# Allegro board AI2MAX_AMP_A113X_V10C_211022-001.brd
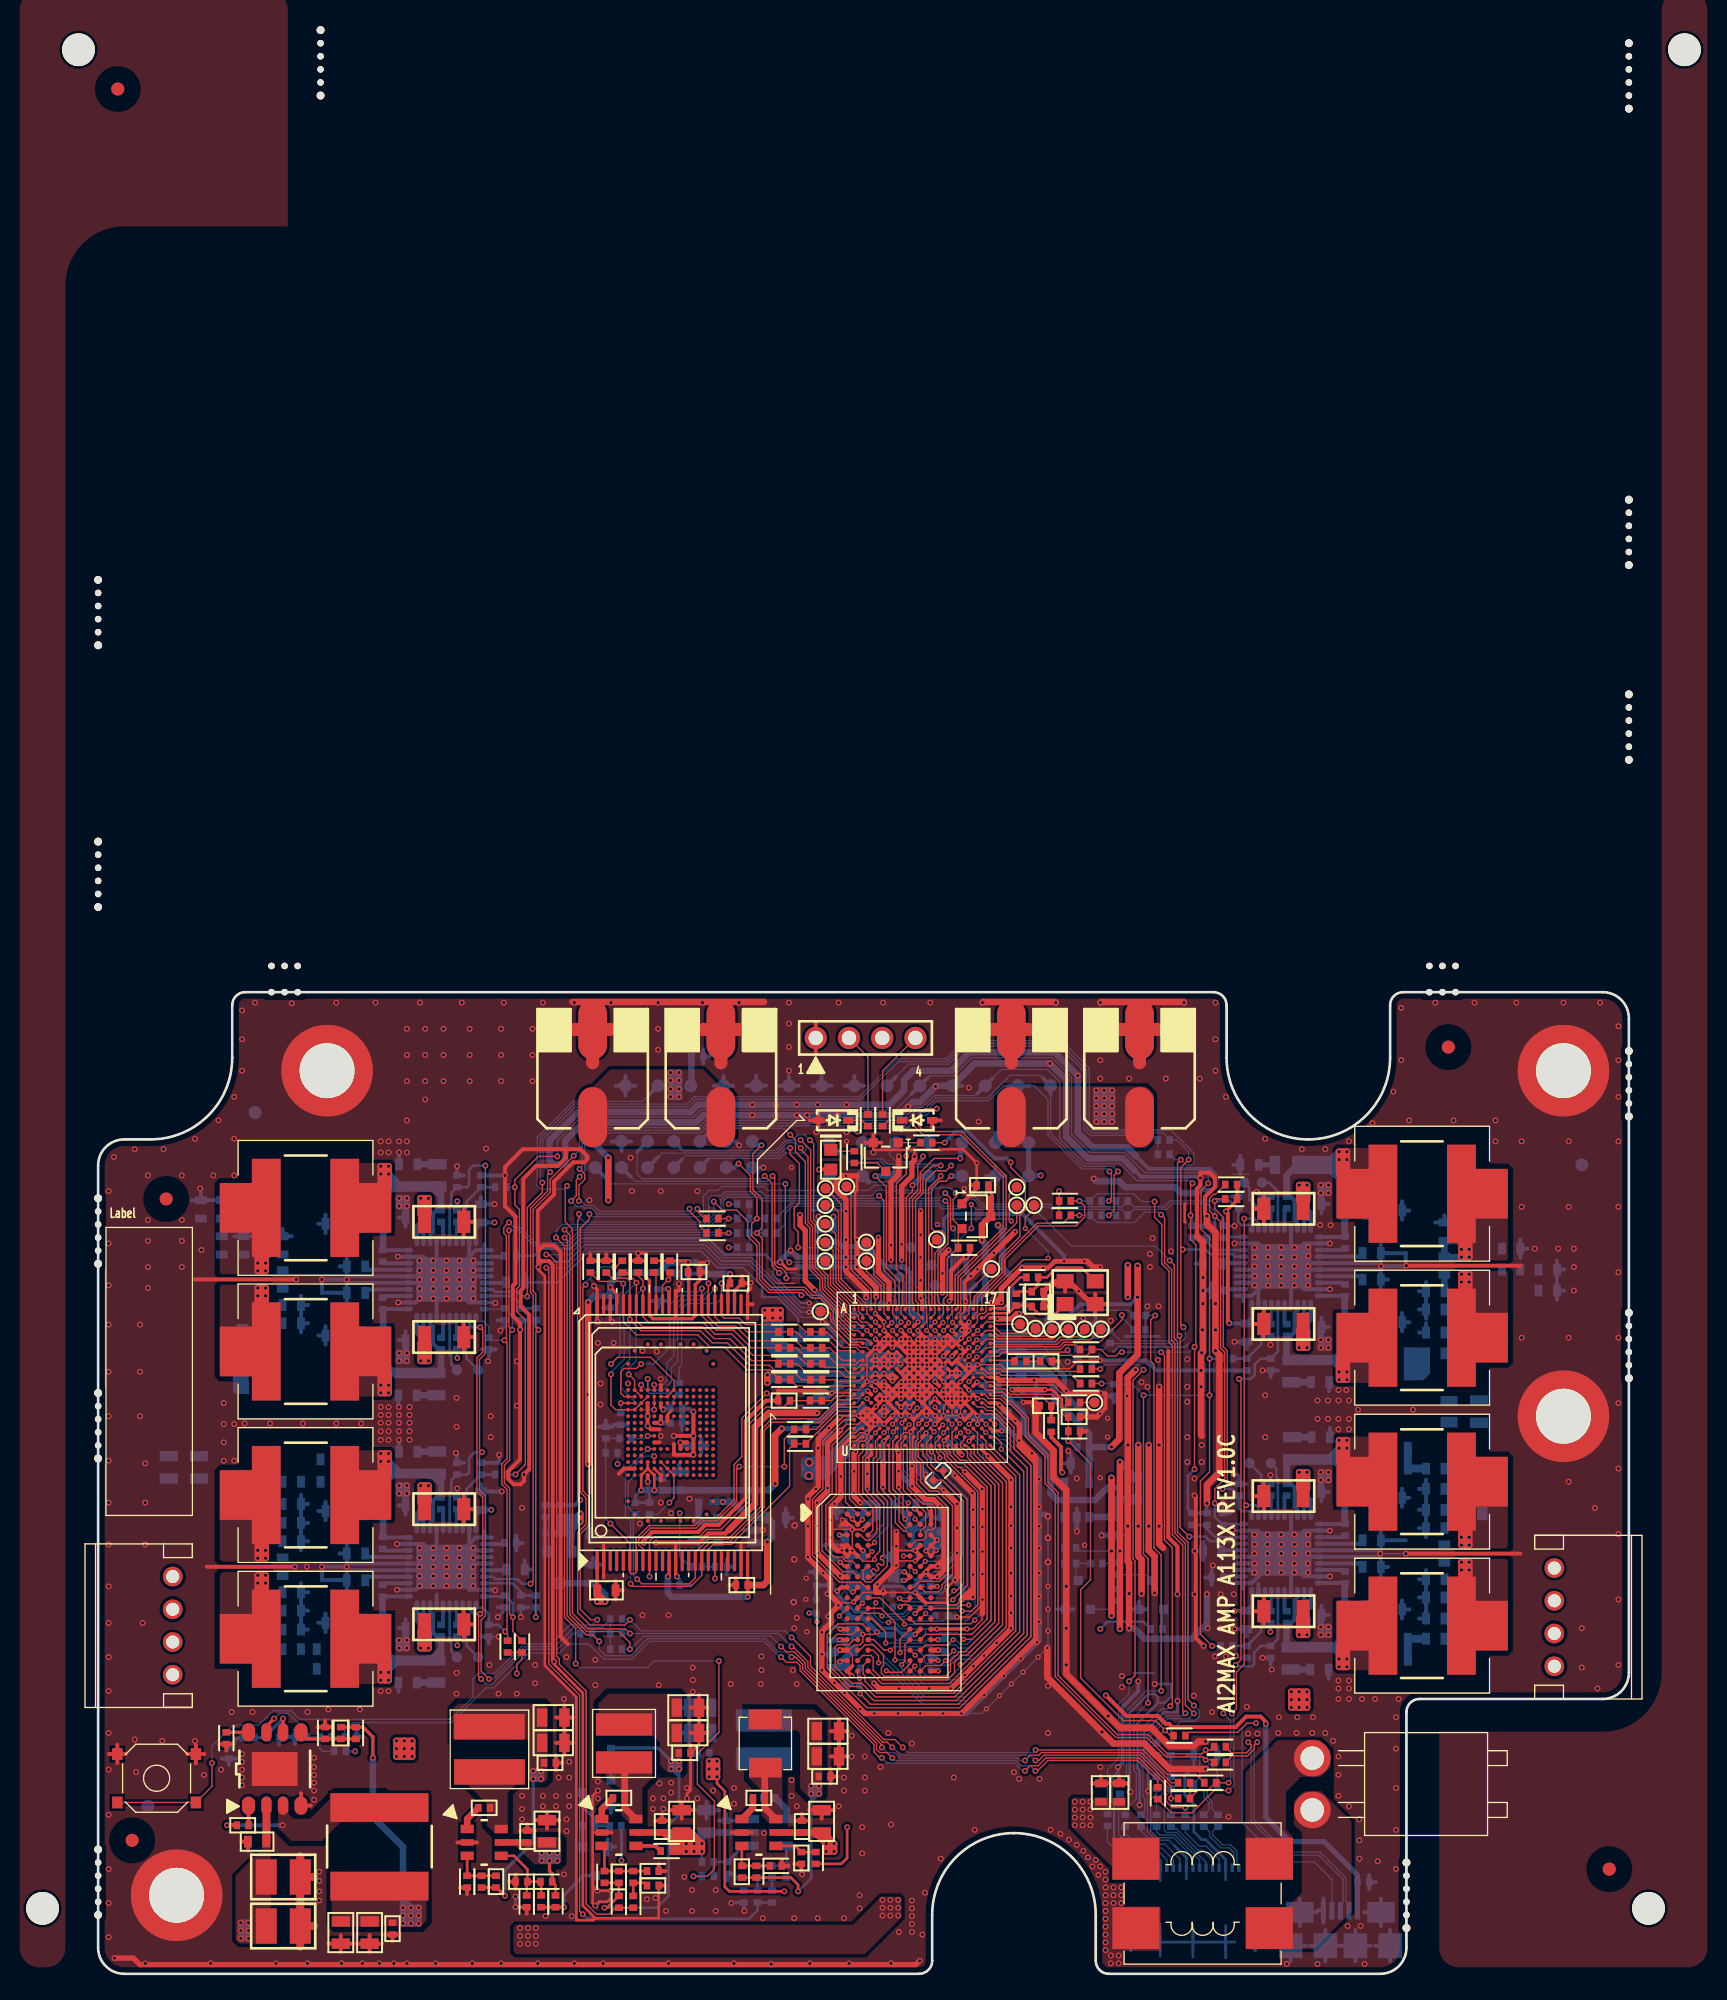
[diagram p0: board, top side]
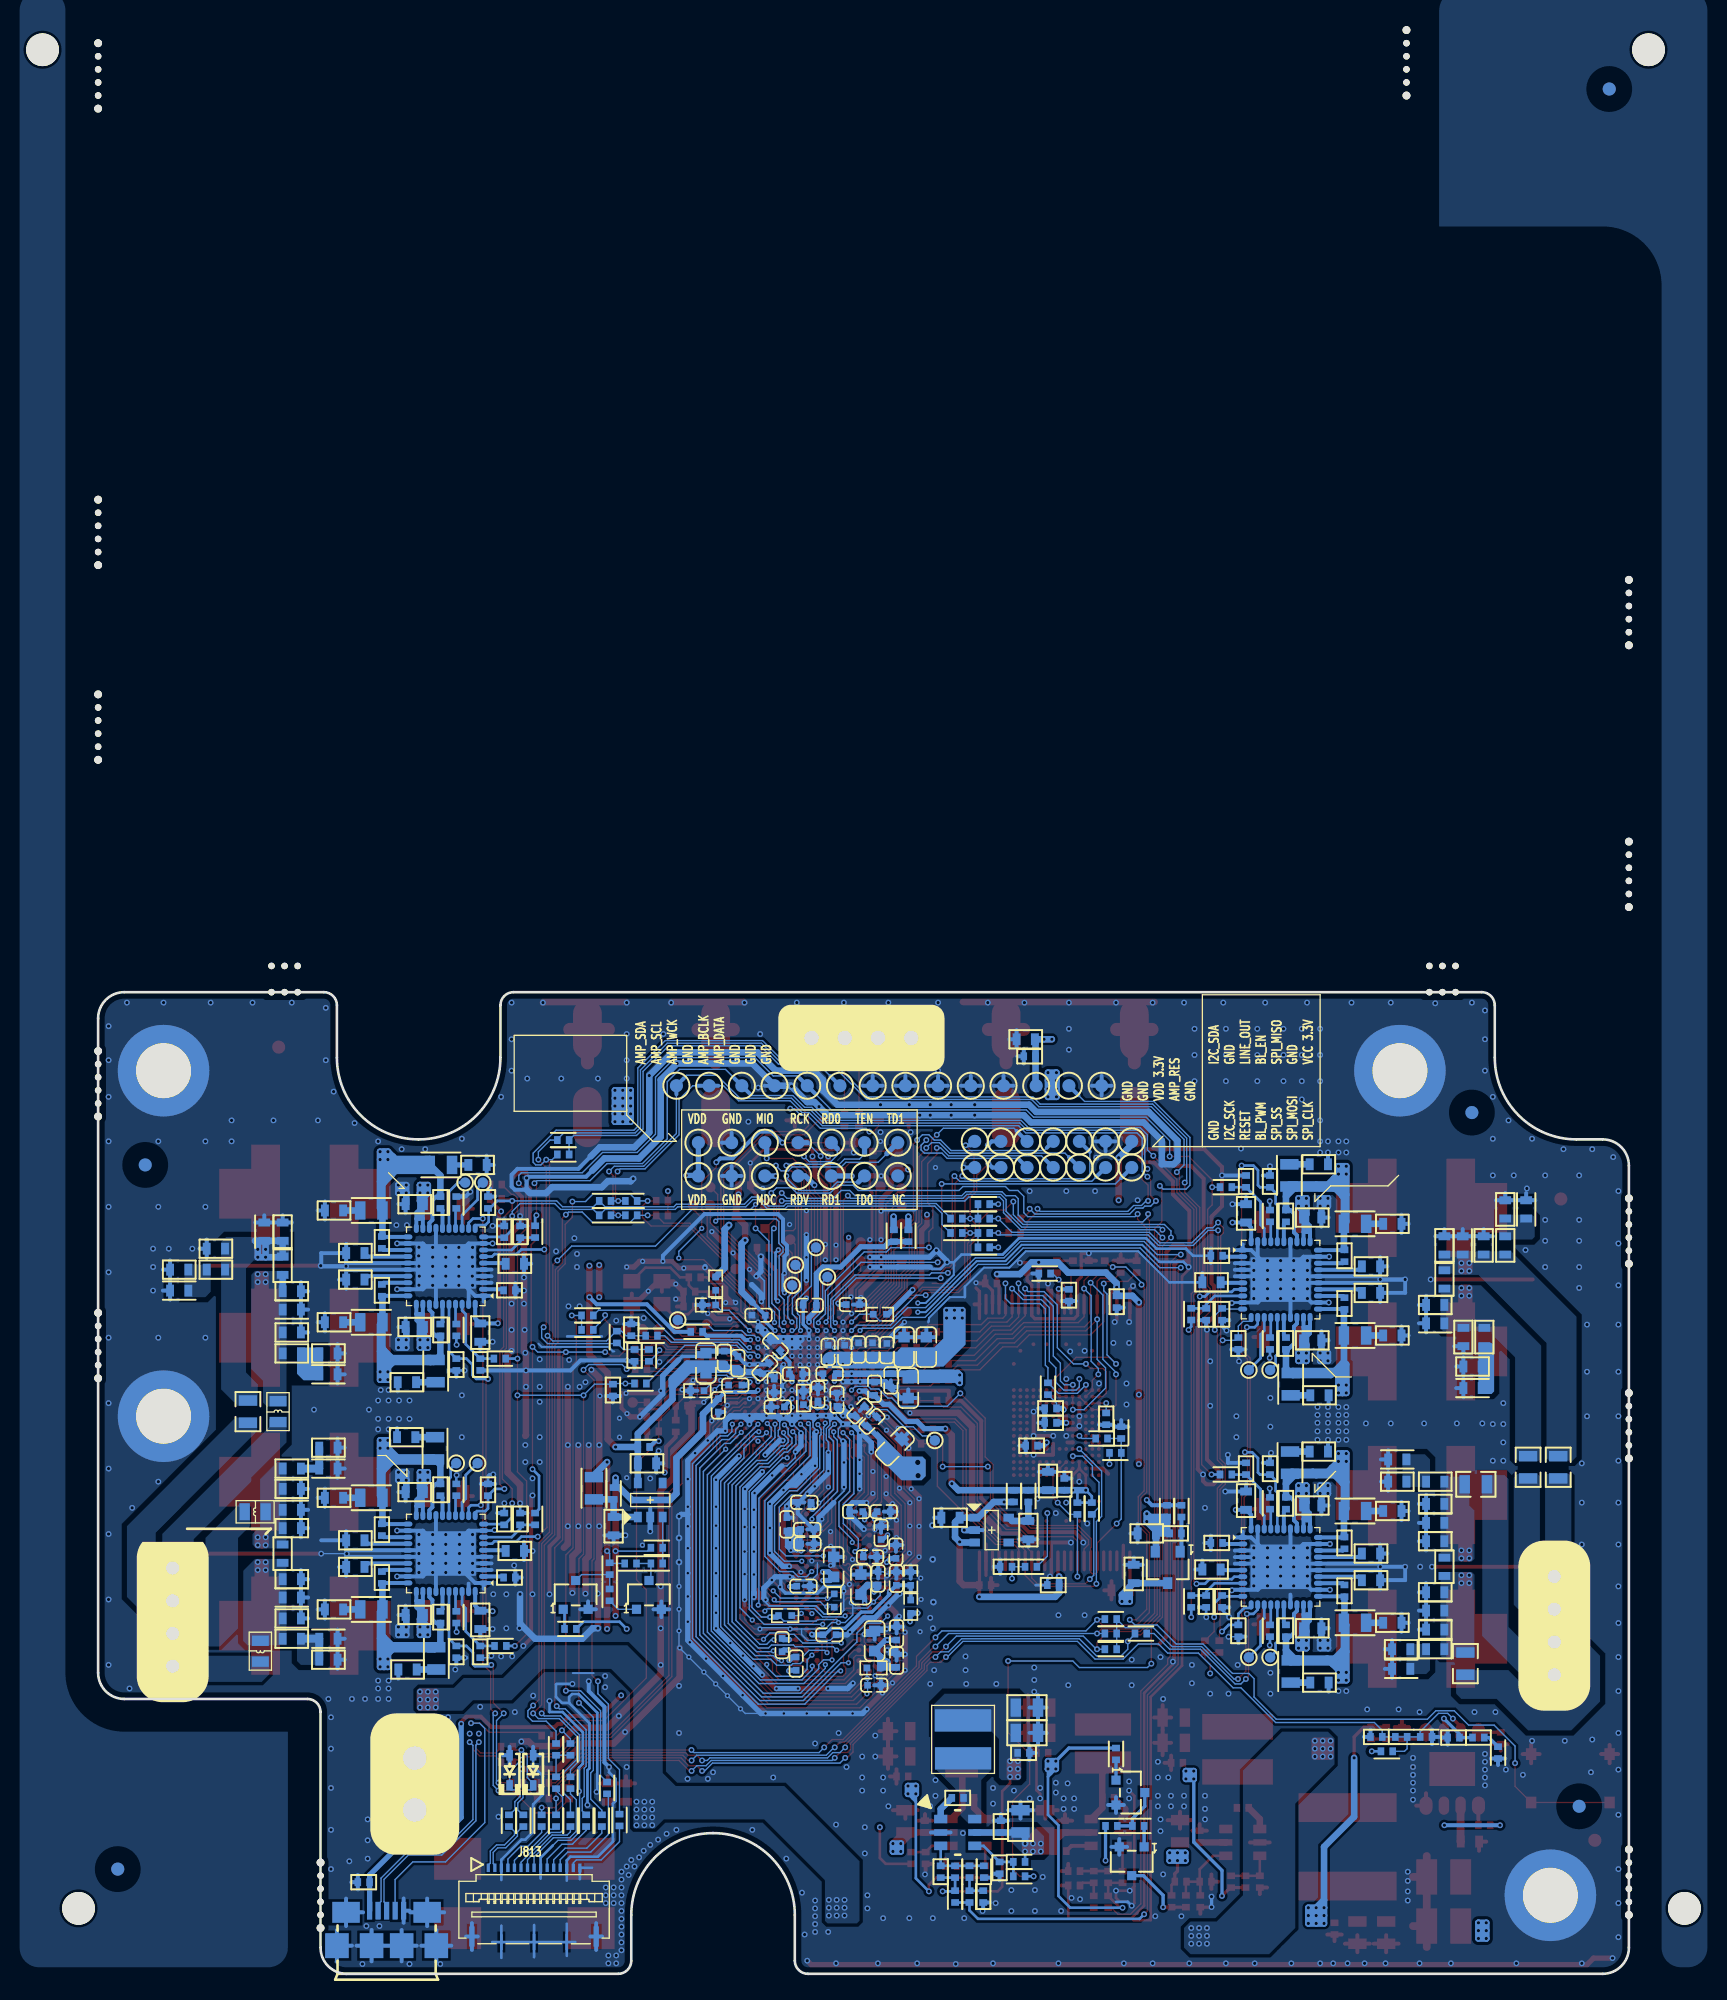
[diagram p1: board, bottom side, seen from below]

Outline 117 x 75 mm; copper layers: TOP, MID1(L2), MID2(L3), BOTTOM. Coordinates in mm from the lower left corner of the outline.
Outline path: 0,61.75 arc(0.59,63.16) 2,63.75 4,63.75 arc(8.42,65.58) 10.25,70 10.25,74 arc(10.54,74.71) 11.25,75 85.25,75 arc(85.96,74.71) 86.25,74 86.25,70 arc(88.08,65.58) 92.5,63.75 arc(96.92,65.58) 98.75,70 98.75,74 arc(99.04,74.71) 99.75,75 115,75 arc(116.41,74.41) 117,73 117,23 arc(116.41,21.59) 115,21 101,21 arc(100.29,20.71) 100,20 100,2 arc(99.41,0.59) 98,0 77.25,0 arc(76.54,0.29) 76.25,1 76.25,4.5 arc(74.42,8.92) 70,10.75 arc(65.58,8.92) 63.75,4.5 63.75,1 arc(63.46,0.29) 62.75,0 2,0 arc(0.59,0.59) 0,2 0,61.75

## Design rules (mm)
net group I2S1: nets BCLK DATA LRCK
net group POWER: nets N21714583 N21714673 N21714779 N21715058 N21715192 N21715315 N21715441 N21715523 N21715623 N21715900 N21716032 N21716155 N21722582 N21722669 N21722769 N21723040 N21723161 N21723285 N21723494 N21723601 N21723713 N21724007 N21727322 N21727332
net group USBOTG_A_DM: nets N21775203 N22017810 USBOTG_A_DM
net group USBOTG_A_DP: nets N21775223 N22060831 USBOTG_A_DP

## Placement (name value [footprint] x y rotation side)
C1  105P/50V/1608  [C1608]  78.05 13.85 90 top
C2  104P/50V/1608  [C1608]  76.65 13.85 90 top
C3  106P/50V/3225  [C3225]  14.15 7.4 0 top
C4  104P/50V/1608  [C1608]  12.15 10.1 180 top
C5  104P/16V/1005  [C1005]  11.05 11.35 180 top
C6  226P/10V/2012  [C2012]  18.55 3.15 270 top
C7  226P/10V/2012  [C2012]  20.75 3.15 270 top
C9  104P/16V/1005  [C1005]  22.5 3.45 90 top
C10  100P/50V/1005  [C1005]  18.55 18.4 90 top
C12  OPEN-104P/16V/1005  [C1005]  19.3 18.1 180 bottom
C13  226P/10V/2012  [C2012]  34.31 10.89 90 top
C14  104P/16V/1005  [C1005]  32.81 10.49 270 top
C15  104P/16V/1005  [C1005]  29.51 12.68 0 top
C16  226P/6.3V/2012  [C2012]  34.79 19.58 0 top
C17  104P/16V/1005  [C1005]  34.54 16.12 180 top
C18  226P/6.3V/2012  [C2012]  34.79 17.65 0 top
C19  330P/50V/1005  [C1005]  30.41 7.04 270 top
C20  104P/16V/1005  [C1005]  32.36 7.04 0 top
C21  106P/6.3V/1608  [C1608]  36.85 33.65 0 bottom
C22  106P/6.3V/1608  [C1608]  37.85 30.55 90 bottom
C23  104P/16V/1005  [C1005]  34.65 33.65 0 bottom
C24  682P/50V/1005  [C1005]  11.5 18.05 0 bottom
C25  100P/50V/1005  [C1005]  13.4 18.05 180 bottom
C30  106P/50V/3225  [C3225]  14.15 3.65 0 top
C51  226P/10V/2012  [C2012]  46.5 11.65 90 bottom
C52  104P/16V/1005  [C1005]  48 11.25 270 bottom
C53  104P/16V/1005  [C1005]  51.3 13.44 180 bottom
C54  226P/6.3V/2012  [C2012]  46.01 20.34 180 bottom
C55  104P/16V/1005  [C1005]  46.27 16.88 0 bottom
C56  226P/6.3V/2012  [C2012]  46.01 18.41 180 bottom
C57  226P/10V/2012  [C2012]  44.6 11.65 90 top
C58  104P/16V/1005  [C1005]  43.1 11.25 270 top
C59  104P/16V/1005  [C1005]  39.8 13.44 0 top
C60  226P/6.3V/2012  [C2012]  45.08 20.34 0 top
C61  104P/16V/1005  [C1005]  44.83 16.88 180 top
C62  226P/6.3V/2012  [C2012]  45.08 18.41 0 top
C63  270P/50V/1005  [C1005]  52.6 7.8 270 bottom
C64  270P/50V/1005  [C1005]  39.8 7.4 270 top
C65  104P/16V/1005  [C1005]  48.1 8.1 90 bottom
C66  102P/16V/1005  [C1005]  49.35 5.9 90 bottom
C67  102P/16V/1005  [C1005]  42.4 6.75 180 top
C68  226P/10V/2012  [C2012]  55.3 11.65 90 top
C69  104P/16V/1005  [C1005]  53.8 11.25 270 top
C70  104P/16V/1005  [C1005]  50.5 13.44 0 top
C71  226P/6.3V/2012  [C2012]  55.78 18.54 0 top
C72  104P/16V/1005  [C1005]  55.53 15.08 180 top
C73  226P/6.3V/2012  [C2012]  55.78 16.61 0 top
C74  330P/50V/1005  [C1005]  49.2 7.8 270 top
C75  OPEN-104P/16V/1005  [C1005]  53.75 8.85 90 top
C76  106P/6.3V/1608  [C1608]  75.05 39 180 bottom
C77  OPEN-106P/6.3V/1608  [C1608]  45.9 33.9 270 bottom
C78  472P/50V/1608  [C1608]  77.6 34.2 270 bottom
C79  OPEN-472P/50V/1608  [C1608]  51.85 34.85 0 bottom
C101  104P/16V/1005  [C0402]  69.6 43.43 90 bottom
C102  105P/6.3V/1005  [C0402]  62.61 51.08 180 bottom
C103  OPEN-150P/50V/1005  [C1005]  77.65 44.6 90 bottom
C104  OPEN-150P/50V/1005  [C1005]  72.45 46.8 180 top
C105  270P/50V/1005  [C1005]  76 47.25 90 bottom
C106  270P/50V/1005  [C1005]  76.25 49.2 270 bottom
C201  105P/6.3V/1608  [C1608]  87.79 48.99 270 bottom
C202  223P/16V/1005  [C1005]  90.84 49.19 270 bottom
C203  271P/50V/1608  [C1608]  93.4 45.2 180 bottom
C204  104P/16V/1005  [C1005]  89.62 46.55 90 bottom
C205  100uF/35V/CLZ  [ECAP_8PI_H10]  47.6 68.8 270 top
C206  104P/50V/1608  [C1608]  92.8 49.42 0 bottom
C207  271P/50V/1608  [C1608]  98.97 49.78 180 bottom
C208  OPEN-104P/16V/1005  [C1005]  85.56 52.22 0 bottom
C209  105P/50V/1608  [C1608]  102.2 52.15 180 bottom
C210  223P/16V/1005  [C1005]  95.31 52.22 90 bottom
C211  105P/16V/1608  [C1608]  97.34 53.04 0 bottom
C213  471P/50V/1608  [C1608]  102.9 54.1 90 bottom
C214  105P/16V/1608  [C1608]  97.34 55.07 0 bottom
C215  223P/16V/1005  [C1005]  95.31 55.88 270 bottom
C216  105P/50V/1608  [C1608]  102.9 56.7 270 bottom
C217  330P/50V/1005  [C1005]  85.96 56.69 270 bottom
C218  105P/6.3V/1608  [C1608]  85.15 54.25 180 bottom
C219  271P/50V/1608  [C1608]  98.97 58.32 180 bottom
C220  223P/16V/1005  [C1005]  90.84 58.93 270 bottom
C221  271P/50V/1608  [C1608]  88 61.8 0 bottom
C222  330P/50V/1005  [C1005]  87.2 58.93 270 bottom
C223  100uF/35V/CLZ  [ECAP_8PI_H10]  37.8 68.8 270 top
C224  104P/50V/1608  [C1608]  92.8 58.8 0 bottom
C225  223P/16V/1005  [C1005]  90.84 27.25 270 bottom
C226  104P/16V/1005  [C1005]  89.62 24.6 90 bottom
C228  271P/50V/1608  [C1608]  93.35 23.25 180 bottom
C229  271P/50V/1608  [C1608]  98.97 27.84 180 bottom
C230  105P/6.3V/1608  [C1608]  87.79 27.04 270 bottom
C231  104P/50V/1608  [C1608]  92.8 27.42 0 bottom
C232  OPEN-104P/16V/1005  [C1005]  85.56 30.28 0 bottom
C233  105P/50V/1608  [C1608]  102.2 30.15 180 bottom
C234  223P/16V/1005  [C1005]  95.31 30.28 90 bottom
C235  105P/16V/1608  [C1608]  97.34 31.09 0 bottom
C237  471P/50V/1608  [C1608]  102.9 32.1 90 bottom
C238  105P/16V/1608  [C1608]  97.34 33.12 0 bottom
C239  223P/16V/1005  [C1005]  95.31 33.93 270 bottom
C240  105P/50V/1608  [C1608]  102.2 34.05 0 bottom
C241  330P/50V/1005  [C1005]  85.96 34.75 270 bottom
C242  105P/6.3V/1608  [C1608]  85.15 32.31 180 bottom
C243  271P/50V/1608  [C1608]  98.97 36.37 180 bottom
C244  223P/16V/1005  [C1005]  90.84 36.98 270 bottom
C245  271P/50V/1608  [C1608]  93.45 41 180 bottom
C246  330P/50V/1005  [C1005]  87.2 36.98 270 bottom
C248  104P/50V/1608  [C1608]  92.8 36.8 0 bottom
C249  OPEN-105P/6.3V/1608  [C1608]  46.1 71.4 0 bottom
C250  OPEN-104P/16V/1005  [C1005]  45.8 70.1 180 bottom
C251  OPEN-330P/50V/1005  [C1005]  87.79 46.55 90 bottom
C252  OPEN-330P/50V/1005  [C1005]  84.74 56.69 270 bottom
C253  OPEN-330P/50V/1005  [C1005]  87.79 24.6 90 bottom
C254  OPEN-330P/50V/1005  [C1005]  84.74 34.75 270 bottom
C255  106P/35V/3216  [C3216]  90.6 49.65 180 top
C256  106P/35V/3216  [C3216]  90.6 58.45 180 top
C257  106P/35V/3216  [C3216]  90.6 27.7 180 top
C258  106P/35V/3216  [C3216]  90.6 36.5 180 top
C259  121P/50V/1608  [C1608]  102.2 49 0 bottom
C260  121P/50V/1608  [C1608]  108 55.4 0 bottom
C261  121P/50V/1608  [C1608]  102.2 27.15 0 bottom
C262  121P/50V/1608  [C1608]  102.2 37.05 180 bottom
C263  OPEN-224P/50V/1608  [C1608]  102.2 47.4 180 bottom
C264  OPEN-224P/50V/1608  [C1608]  99.4 47.4 180 bottom
C265  OPEN-224P/50V/1608  [C1608]  110.8 53.8 180 bottom
C266  OPEN-224P/50V/1608  [C1608]  108 53.8 180 bottom
C267  OPEN-224P/50V/1608  [C1608]  102.2 25.6 180 bottom
C268  OPEN-224P/50V/1608  [C1608]  99.4 24 180 bottom
C269  OPEN-224P/50V/1608  [C1608]  99.4 40.2 0 bottom
C270  OPEN-224P/50V/1608  [C1608]  102.2 38.6 0 bottom
C301  105P/6.3V/1608  [C1608]  29.26 36.15 90 bottom
C302  223P/16V/1005  [C1005]  26.21 35.95 90 bottom
C303  271P/50V/1608  [C1608]  23.7 39.9 0 bottom
C304  104P/16V/1005  [C1005]  27.43 38.59 270 bottom
C305  100uF/35V/CLZ  [ECAP_8PI_H10]  69.8 68.8 270 top
C306  104P/50V/1608  [C1608]  24.2 35.78 180 bottom
C307  271P/50V/1608  [C1608]  18.08 35.36 0 bottom
C308  OPEN-104P/16V/1005  [C1005]  31.5 32.92 180 bottom
C309  105P/50V/1608  [C1608]  14.8 33.05 0 bottom
C310  223P/16V/1005  [C1005]  21.74 32.92 270 bottom
C311  105P/16V/1608  [C1608]  19.71 32.11 180 bottom
C313  471P/50V/1608  [C1608]  14.1 31.1 270 bottom
C314  105P/16V/1608  [C1608]  19.71 30.07 180 bottom
C315  223P/16V/1005  [C1005]  21.74 29.26 90 bottom
C316  105P/50V/1608  [C1608]  14.8 29.15 180 bottom
C317  330P/50V/1005  [C1005]  31.09 28.45 90 bottom
C318  105P/6.3V/1608  [C1608]  31.9 30.89 0 bottom
C319  271P/50V/1608  [C1608]  18.08 26.82 0 bottom
C320  223P/16V/1005  [C1005]  26.21 26.21 90 bottom
C321  271P/50V/1608  [C1608]  23.65 22.25 0 bottom
C322  330P/50V/1005  [C1005]  29.85 26.21 90 bottom
C323  100uF/35V/CLZ  [ECAP_8PI_H10]  79.6 68.8 270 top
C324  104P/50V/1608  [C1608]  24.2 26.4 180 bottom
C325  223P/16V/1005  [C1005]  26.21 57.9 90 bottom
C326  104P/16V/1005  [C1005]  27.43 60.54 270 bottom
C328  271P/50V/1608  [C1608]  23.7 61.85 0 bottom
C329  271P/50V/1608  [C1608]  18.08 57.3 0 bottom
C330  105P/6.3V/1608  [C1608]  29.26 58.1 90 bottom
C331  104P/50V/1608  [C1608]  24.2 57.78 180 bottom
C332  OPEN-104P/16V/1005  [C1005]  31.5 54.86 180 bottom
C333  105P/50V/1608  [C1608]  14.1 55.65 90 bottom
C334  223P/16V/1005  [C1005]  21.74 54.86 270 bottom
C335  105P/16V/1608  [C1608]  19.71 54.05 180 bottom
C337  471P/50V/1608  [C1608]  14.1 53.05 270 bottom
C338  105P/16V/1608  [C1608]  19.71 52.02 180 bottom
C339  223P/16V/1005  [C1005]  21.74 51.21 90 bottom
C340  105P/50V/1608  [C1608]  14.8 51.1 180 bottom
C341  330P/50V/1005  [C1005]  31.09 50.39 90 bottom
C342  105P/6.3V/1608  [C1608]  31.9 52.83 0 bottom
C343  271P/50V/1608  [C1608]  18.08 48.77 0 bottom
C344  223P/16V/1005  [C1005]  26.21 48.16 90 bottom
C345  271P/50V/1608  [C1608]  23.65 44.2 0 bottom
C346  330P/50V/1005  [C1005]  29.85 48.16 90 bottom
C348  104P/50V/1608  [C1608]  24.2 48.4 180 bottom
C349  OPEN-330P/50V/1005  [C1005]  29.26 38.59 270 bottom
C350  OPEN-330P/50V/1005  [C1005]  32.31 28.45 90 bottom
C351  OPEN-330P/50V/1005  [C1005]  29.26 60.54 270 bottom
C352  OPEN-330P/50V/1005  [C1005]  32.31 50.39 90 bottom
C353  106P/35V/3216  [C3216]  26.45 35.5 0 top
C354  106P/35V/3216  [C3216]  26.45 26.7 0 top
C355  106P/35V/3216  [C3216]  26.45 57.45 0 top
C356  106P/35V/3216  [C3216]  26.45 48.65 0 top
C357  121P/50V/1608  [C1608]  14.8 35.9 180 bottom
C358  121P/50V/1608  [C1608]  14.8 26.3 0 bottom
C359  121P/50V/1608  [C1608]  11.1 55.65 270 bottom
C360  121P/50V/1608  [C1608]  12.65 48.65 270 bottom
C361  OPEN-224P/50V/1608  [C1608]  14.8 37.6 0 bottom
C362  OPEN-224P/50V/1608  [C1608]  17.7 37.6 0 bottom
C363  OPEN-224P/50V/1608  [C1608]  17.4 24.8 180 bottom
C364  OPEN-224P/50V/1608  [C1608]  14.8 24.8 180 bottom
C365  OPEN-224P/50V/1608  [C1608]  9.45 55.65 90 bottom
C366  OPEN-224P/50V/1608  [C1608]  9.45 58.4 90 bottom
C367  OPEN-224P/50V/1608  [C1608]  11.95 46.4 180 bottom
C368  OPEN-224P/50V/1608  [C1608]  11.05 48.65 90 bottom
FB201  CIS21J121NE  [CIS2012]  105.55 42.95 90 bottom
FB202  120ohm/5A/2012  [BLM21]  103.25 42.95 90 bottom
FB203  120ohm/5A/2012  [BLM21]  104.6 24.65 270 bottom
FB204  120ohm/5A/2012  [BLM21]  105 35.3 0 bottom
FB301  CIS21J121NE  [CIS2012]  12.5 23.7 90 bottom
FB302  CIS21J121NE  [CIS2012]  11.7 37.4 0 bottom
FB303  CIS21J121NE  [CIS2012]  5.4 38.7 270 bottom
FB304  CIS21J121NE  [CIS2012]  7.7 38.7 270 bottom
J803  S4B-EH(LF)(SN)  [SXB-EH-4P]  115 27.25 270 top
J804  S4B-EH(LF)(SN)  [SXB-EH-4P]  2 26.6 90 top
J812  -  [51318-0023L-001]  100 14.5 270 top
J813  FH41-15S-0.5SH(05)  [FH41-15S-0_5SH]  83.68 4.9 0 bottom
J814  10118192-0002LF  [MICRO_USB_10118192]  94.95 2.5 180 bottom
L1  SWPA8040S100MT  [SWPA8040S]  21.5 9.7 0 top
L2  MLPS-5035-4R7M-E-EH  [COIL_MLPS5035]  29.91 17.15 180 top
L51  LVS404018-2R2M  [COIL_LVS404018]  50.89 17.91 0 bottom
L52  LVS404018-2R2M  [COIL_LVS404018]  40.2 17.6 180 top
L53  SMPI0402BW-3R3M  [COIL_SMPI0402BW]  51 17.6 90 top
L201  SPH10040-100M  [COIL_SPH10040]  101.2 48.6 0 top
L202  SPH10040-100M  [COIL_SPH10040]  101.2 59.6 0 top
L203  SPH10040-100M  [COIL_SPH10040]  101.2 26.6 0 top
L204  SPH10040-100M  [COIL_SPH10040]  101.2 37.6 0 top
L211  OPEN-SWPA8065S100NT  [SWPA8065S]  101.2 48.6 90 top
L212  OPEN-SWPA8065S100NT  [SWPA8065S]  101.2 59.6 90 top
L213  OPEN-SWPA8065S100NT  [SWPA8065S]  101.2 26.6 90 top
L214  OPEN-SWPA8065S100NT  [SWPA8065S]  101.2 37.6 90 top
L301  SPH10040-100M  [COIL_SPH10040]  15.85 36.58 180 top
L302  SPH10040-100M  [COIL_SPH10040]  15.85 25.6 180 top
L303  SPH10040-100M  [COIL_SPH10040]  15.85 58.52 180 top
L304  SPH10040-100M  [COIL_SPH10040]  15.85 47.55 180 top
L311  OPEN-SWPA8065S100NT  [SWPA8065S]  15.85 36.58 270 top
L312  OPEN-SWPA8065S100NT  [SWPA8065S]  15.85 25.6 270 top
L313  OPEN-SWPA8065S100NT  [SWPA8065S]  15.85 58.52 270 top
L314  OPEN-SWPA8065S100NT  [SWPA8065S]  15.85 47.55 270 top
NOREF  -  []  -20 -16 0 top
NOREF#2  -  [unnamed#2]  115.5 8 0 top
NOREF#3  -  [unnamed#2]  6 6 0 top
NOREF#4  -  []  -62 80 0 top
NOREF#5  -  [unnamed#3]  117 95.25 90 top
NOREF#6  -  [unnamed#3]  117 110.13 90 top
NOREF#7  -  []  140 -71 90 top
NOREF#8  -  []  0 -2 0 top
NOREF#9  -  []  140 -32 90 top
NOREF#10  -  [unnamed#3]  0 104 270 top
NOREF#11  -  []  -62 -41.75 90 top
NOREF#12  -  [unnamed#3]  117 48 90 top
NOREF#13  -  [unnamed#3]  117 145 90 top
NOREF#14  -  [unnamed#2]  5.2 59.2 0 top
NOREF#15  -  []  -62 -41.75 0 top
NOREF#16  -  [unnamed#4]  102.75 75 180 top
NOREF#17  -  [unnamed#5]  118.5 5 0 top
NOREF#18  -  [unnamed#3]  17 146 270 top
NOREF#19  -  []  -62 -9.75 90 top
NOREF#20  -  [unnamed#2]  112 69 0 top
NOREF#21  -  [unnamed#5]  121.25 147 0 top
NOREF#22  -  [unnamed#2]  103.2 70.8 0 top
NOREF#23  -  []  -62 -71 0 top
NOREF#24  -  []  -4.5 0 90 top
NOREF#25  -  []  135 -81 90 top
NOREF#26  -  [unnamed#3]  0 41.88 270 top
NOREF#27  -  []  -6.5 150 0 top
NOREF#28  -  [unnamed#2]  1.5 144 0 top
NOREF#29  -  []  -62 5.45 0 top
NOREF#30  -  [unnamed#3]  0 56.75 270 top
NOREF#31  -  [unnamed#3]  0 84 270 top
NOREF#32  -  []  0 -14 90 top
NOREF#33  -  []  63.75 0 90 top
NOREF#34  -  [unnamed#3]  0 7 270 top
NOREF#35  -  [unnamed#2]  2.6 10.2 0 top
NOREF#36  -  [unnamed#2]  17.5 69 0 top
NOREF#37  -  [unnamed#4]  102.75 77 0 top
NOREF#38  -  []  -62 -71 90 top
NOREF#39  -  []  0 44.01 0 top
NOREF#40  -  [unnamed#5]  -1.5 147 0 top
NOREF#41  -  [unnamed#4]  14.25 75 180 top
NOREF#42  -  [unnamed#3]  100 6 90 top
NOREF#43  -  []  135 -81 90 top
NOREF#44  -  [unnamed#2]  112 42.6 0 top
NOREF#45  -  [unnamed#5]  -4.25 5 0 top
NOREF#46  -  [unnamed#4]  14.25 77 0 top
NOREF#47  -  []  71.61 -71 90 top
NOREF#48  -  [unnamed#3]  117 68 90 top
NOREF#49  -  [unnamed#2]  115.5 8 180 bottom
NOREF#50  -  [unnamed#2]  12 65.8 180 bottom
NOREF#51  -  [unnamed#2]  113.4 61.8 180 bottom
NOREF#52  -  [unnamed#2]  3.8 12.8 180 bottom
NOREF#53  -  [unnamed#2]  1.5 144 180 bottom
Q1  WPM3401  [SOT23_LRT_W2_7_WPM3401]  35.25 31.05 0 bottom
Q2  OPEN-MMBT3904  [SOT23_LRT_MMBT3904]  38 8.6 0 bottom
Q3  OPEN-MMBT3904  [SOT23_LRT_MMBT3904]  38.1 13.85 270 bottom
Q4  MMBT3904  [SOT23_LRT_MMBT3904]  80.5 28.95 180 bottom
Q5  MMBT3904  [SOT23_LRT_MMBT3904]  74.9 28.95 180 bottom
R1  OPEN-204/F/1005  [R1005]  18.5 17 0 bottom
R2  OPEN-000/1005  [R1005]  17.4 18.1 180 bottom
R3  4992/F/1005  [R1005]  15.5 18.1 0 bottom
R6  104/1005  [R1005]  34.26 7.04 0 top
R7  OPEN-473/1005  [R1005]  32.76 5.54 90 top
R8  104/F/1005  [R1005]  29.31 7.04 270 top
R9  2212/F/1005  [R1005]  28.21 7.04 90 top
R10  5232/F/1005  [R1005]  19.7 18.4 90 top
R11  103/F/1005  [R1005]  17.35 18.4 270 top
R12  OPEN-103/1005  [R1005]  35.3 35.35 270 bottom
R13  472/1005  [R1005]  34.2 35.35 270 bottom
R15  OPEN-103/1005  [R1005]  39.2 16.8 90 bottom
R16  OPEN-103/1005  [R1005]  37.5 11.3 0 bottom
R17  OPEN-103/1005  [R1005]  39.55 11.3 180 bottom
R18  OPEN-103/1005  [R1005]  34.96 5.54 270 top
R19  OPEN-000/1005  [R1005]  33.86 5.54 270 top
R21  104/F/1005  [R1005]  9.8 18 90 top
R22  332/F/1005  [R1005]  10 16.9 90 bottom
R51  104/F/1005  [R1005]  51.5 7.8 270 bottom
R52  472/1005  [R1005]  43.45 9.38 0 top
R53  124/F/1005  [R1005]  38.7 7.4 270 top
R54  472/1005  [R1005]  46.6 7.45 0 bottom
R55  105/F/1005  [R1005]  50.4 7.8 270 bottom
R56  104/F/1005  [R1005]  50.4 5.9 270 bottom
R57  125/F/1005  [R1005]  40.9 7.4 270 top
R58  124/F/1005  [R1005]  40.9 5.5 270 top
R59  1213/F/1005  [R1005]  49.3 7.8 90 bottom
R60  1623/F/1005  [R1005]  42.4 7.85 180 top
R61  124/F/1005  [R1005]  50.3 7.8 270 top
R62  102/1005  [R1005]  54.85 8.85 90 top
R63  9532/F/1005  [R1005]  51.8 8.25 180 top
R101  OPEN-000/1005  [R1005]  74.6 43.65 0 top
R102  OPEN-330/1005  [R1005]  75.5 46.2 0 top
R103  101/1005  [R1005]  79.6 49.2 0 bottom
R104  101/1005  [R1005]  79.6 50.3 0 bottom
R105  000/1005  [R1005]  56.18 56.39 270 bottom
R106  OPEN-000/1005  [R1005]  55.07 56.39 270 bottom
R107  101/1005  [R1005]  75.5 45.1 0 top
R108  101/1005  [R1005]  70.5 46.8 0 top
R109  101/1005  [R1005]  74.9 47.25 90 bottom
R110  101/1005  [R1005]  74.7 48.75 0 bottom
R201  472/1005  [R1005]  89.62 49.19 270 bottom
R202  6R8/F/2012  [R2012]  91.2 46.05 90 bottom
R203  6R8/F/2012  [R2012]  96.12 49.78 0 bottom
R204  472/F/1608  [R1608]  102.2 50.75 0 bottom
R205  472/F/1608  [R1608]  104.3 56.7 90 bottom
R206  6R8/F/2012  [R2012]  96.12 58.32 180 bottom
R207  472/1005  [R1005]  89.62 58.93 270 bottom
R208  6R8/F/2012  [R2012]  90.8 61.8 180 bottom
R209  000/1005  [R1005]  76.25 59.05 0 bottom
R210  000/1005  [R1005]  76.25 57.95 0 bottom
R211  OPEN-101/1005  [R1005]  51.4 57.7 0 bottom
R212  OPEN-101/1005  [R1005]  51.4 56.6 0 bottom
R213  6R8/F/2012  [R2012]  91.15 24.1 90 bottom
R214  472/1005  [R1005]  89.62 27.25 270 bottom
R215  101/1005  [R1005]  83 13.4 0 top
R216  OPEN-101/1005  [R1005]  83 14.6 0 top
R217  6R8/F/2012  [R2012]  96.12 27.84 0 bottom
R219  OPEN-101/1005  [R1005]  81 13.8 270 top
R220  472/F/1608  [R1608]  102.2 28.75 0 bottom
R221  472/F/1608  [R1608]  102.2 35.45 180 bottom
R222  6R8/F/2012  [R2012]  96.12 36.37 180 bottom
R223  472/1005  [R1005]  89.62 36.98 270 bottom
R224  6R8/F/2012  [R2012]  91.25 40.15 90 bottom
R225  OPEN-101/1005  [R1005]  81.45 63.7 0 bottom
R226  OPEN-101/1005  [R1005]  81.45 62.6 0 bottom
R227  101/1005  [R1005]  86.3 47 0 bottom
R228  101/1005  [R1005]  83.6 56.7 270 bottom
R229  101/1005  [R1005]  86.25 25.05 0 bottom
R230  101/1005  [R1005]  83.6 34.75 270 bottom
R231  OPEN-330/1005  [R1005]  77.35 48.65 270 bottom
R233  OPEN-100/F/1608  [R1608]  99.4 45.8 0 bottom
R234  OPEN-100/F/1608  [R1608]  110.8 52.2 0 bottom
R235  OPEN-100/F/1608  [R1608]  99.4 25.6 0 bottom
R236  OPEN-100/F/1608  [R1608]  99.4 38.6 180 bottom
R238  101/1005  [R1005]  78.25 59.05 0 bottom
R239  101/1005  [R1005]  78.25 57.95 0 bottom
R240  OPEN-101/1005  [R1005]  85 14.6 0 top
R301  472/1005  [R1005]  27.43 35.95 90 bottom
R302  6R8/F/2012  [R2012]  25.9 39.05 270 bottom
R303  6R8/F/2012  [R2012]  20.93 35.36 180 bottom
R304  472/F/1608  [R1608]  14.8 34.45 180 bottom
R305  472/F/1608  [R1608]  14.8 27.75 0 bottom
R306  6R8/F/2012  [R2012]  20.93 26.82 0 bottom
R307  472/1005  [R1005]  27.43 26.21 90 bottom
R308  6R8/F/2012  [R2012]  25.85 23.1 270 bottom
R309  101/1005  [R1005]  46.95 57.7 0 top
R310  101/1005  [R1005]  46.95 56.6 0 top
R311  OPEN-101/1005  [R1005]  49.3 57.7 180 bottom
R312  OPEN-101/1005  [R1005]  49.3 56.6 180 bottom
R313  6R8/F/2012  [R2012]  25.95 61 270 bottom
R314  472/1005  [R1005]  27.43 57.9 90 bottom
R315  101/1005  [R1005]  39.6 26 180 bottom
R316  OPEN-101/1005  [R1005]  39.6 24.8 180 bottom
R317  6R8/F/2012  [R2012]  20.93 57.3 180 bottom
R319  472/F/1608  [R1608]  12.7 55.65 270 bottom
R320  OPEN-101/1005  [R1005]  37.3 26 180 bottom
R321  472/F/1608  [R1608]  14.8 49.7 0 bottom
R322  6R8/F/2012  [R2012]  20.93 48.77 0 bottom
R323  472/1005  [R1005]  27.43 48.16 90 bottom
R324  6R8/F/2012  [R2012]  25.85 45.05 270 bottom
R325  101/1005  [R1005]  30.8 38.15 180 bottom
R326  101/1005  [R1005]  33.45 28.45 90 bottom
R327  101/1005  [R1005]  30.8 60.1 180 bottom
R328  101/1005  [R1005]  33.45 50.4 90 bottom
R329  103/1005  [R1005]  77.9 30.95 270 bottom
R330  103/1005  [R1005]  76.3 31.35 180 bottom
R331  000/1005  [R1005]  74.3 31.35 0 bottom
R332  103/1005  [R1005]  77.9 28.95 90 bottom
R333  103/1005  [R1005]  80.9 26.35 180 bottom
R334  000/2012  [R2012]  79.1 37.1 270 bottom
R335  OPEN-000/1005  [R1005]  77.6 36.7 270 bottom
R336  OPEN-000/1005  [R1005]  74.3 32.55 180 bottom
R337  OPEN-472/1005  [R1005]  46.6 8.55 180 bottom
R338  OPEN-101/1005  [R1005]  39.6 27.1 180 bottom
R339  OPEN-100/F/1608  [R1608]  17.7 39.3 180 bottom
R340  OPEN-100/F/1608  [R1608]  17.4 23.3 0 bottom
R341  OPEN-100/F/1608  [R1608]  7.85 58.4 270 bottom
R342  OPEN-100/F/1608  [R1608]  11.95 44.75 0 bottom
R343  101/1005  [R1005]  75.55 45.1 0 bottom
R344  101/1005  [R1005]  75.5 47.7 0 top
R348  102/1005  [R1005]  86.6 60.3 180 top
R349  102/1005  [R1005]  86.6 59.2 180 top
R350  102/1005  [R1005]  32.4 25 90 top
R351  102/1005  [R1005]  31.3 25 90 top
T1  BPPM00121190172X0F  [COIL_BPPM00121190]  84.42 6.14 0 top
T101  T_POINT_R_1  [TP0_8PI]  76.15 43.65 0 top
T102  T_POINT_R_1  [TP0_8PI]  75.4 49.25 0 top
T103  T_POINT_R_1  [TP0_8PI]  76.65 49.25 0 top
T104  T_POINT_R_1  [TP0_8PI]  72.9 49.25 0 top
T105  T_POINT_R_1  [TP0_8PI]  74.15 49.25 0 top
T106  T_POINT_R_1  [TP0_8PI]  71.65 49.3 0 top
T107  T_POINT_R_1  [TP0_8PI]  72.7 49.95 180 bottom
T108  T_POINT_R_1  [TP0_8PI]  70.46 49.63 0 top
T109  T_POINT_R_1  [TP0_8PI]  58.72 54.46 0 top
T110  T_POINT_R_1  [TP0_8PI]  58.72 55.88 0 top
T111  T_POINT_R_1  [TP0_8PI]  55.58 57.3 0 top
T112  T_POINT_R_1  [TP0_8PI]  55.58 58.72 0 top
T113  T_POINT_R_1  [TP0_8PI]  57.2 60.15 0 top
T114  T_POINT_R_1  [TP0_8PI]  55.6 60 0 top
T115  T_POINT_R_1  [TP0_8PI]  55.58 55.88 0 top
T116  T_POINT_R_1  [TP0_8PI]  55.58 54.46 0 top
T120  T_POINT_R_1  [TP0_8PI]  64.1 56.1 0 top
T125  T_POINT_R_1  [TP0_8PI]  62.13 55.49 180 bottom
T126  T_POINT_R_1  [TP0_8PI]  61.26 53.24 180 bottom
T127  T_POINT_R_1  [TP0_8PI]  63.95 52.6 180 bottom
T129  T_POINT_R_1  [TP1_0PI]  71.12 60.96 180 bottom
T201  T_POINT_R_1  [TP0_8PI]  87.6 60.45 180 bottom
T202  T_POINT_R_1  [TP0_8PI]  88.95 60.45 180 bottom
T203  T_POINT_R_1  [TP0_8PI]  88 39.01 180 bottom
T204  T_POINT_R_1  [TP0_8PI]  89.63 39.01 180 bottom
T301  T_POINT_R_1  [TP0_8PI]  29.05 24.18 0 bottom
T302  T_POINT_R_1  [TP0_8PI]  27.42 24.18 0 bottom
T303  T_POINT_R_1  [TP0_8PI]  29.05 46.13 0 bottom
T304  T_POINT_R_1  [TP0_8PI]  27.42 46.13 0 bottom
T305  T_POINT_R_1  [TP1_0PI]  72.8 67.85 0 bottom
T306  T_POINT_R_1  [TP1_0PI]  70.3 67.85 0 bottom
T307  T_POINT_R_1  [TP1_0PI]  67.8 67.85 0 bottom
T308  T_POINT_R_1  [TP1_0PI]  65.3 67.85 0 bottom
T309  T_POINT_R_1  [TP1_0PI]  62.8 67.85 0 bottom
T310  T_POINT_R_1  [TP1_0PI]  60.3 67.85 0 bottom
T311  T_POINT_R_1  [TP1_0PI]  57.8 67.85 0 bottom
T312  T_POINT_R_1  [TP1_0PI]  55.3 67.85 0 bottom
T313  T_POINT_R_1  [TP1_0PI]  52.8 67.85 0 bottom
T314  T_POINT_R_1  [TP1_0PI]  50.3 67.85 0 bottom
T315  T_POINT_R_1  [TP1_0PI]  47.8 67.85 0 bottom
T316  T_POINT_R_1  [TP1_0PI]  45.3 67.85 0 bottom
T317  T_POINT_R_1  [TP1_0PI]  42.8 67.85 0 bottom
T318  T_POINT_R_1  [TP1_0PI]  40.3 67.85 0 bottom
T319  T_POINT_R_1  [TP1_0PI]  71.12 63.5 180 bottom
T320  T_POINT_R_1  [TP1_0PI]  68.58 60.96 180 bottom
T321  T_POINT_R_1  [TP1_0PI]  68.58 63.5 180 bottom
T322  T_POINT_R_1  [TP1_0PI]  66.04 60.96 180 bottom
T323  T_POINT_R_1  [TP1_0PI]  66.04 63.5 180 bottom
T324  T_POINT_R_1  [TP1_0PI]  63.5 60.96 180 bottom
T325  T_POINT_R_1  [TP1_0PI]  63.5 63.5 180 bottom
T326  T_POINT_R_1  [TP1_0PI]  60.96 60.96 180 bottom
T327  T_POINT_R_1  [TP1_0PI]  60.96 63.5 180 bottom
T328  T_POINT_R_1  [TP1_0PI]  58.42 60.96 180 bottom
T329  T_POINT_R_1  [TP1_0PI]  58.42 63.5 180 bottom
T330  T_POINT_R_1  [TP1_0PI]  55.88 60.96 180 bottom
T331  T_POINT_R_1  [TP1_0PI]  55.88 63.5 180 bottom
U1  -  [A113X]  62.99 45.57 0 top
U2  TMI3343B  [SOP8_EP_TMI3343B]  13.5 15.65 0 top
U3  TMI3252S  [SOT23-6P_TMI3252S]  29.51 10.04 270 top
U51  TMI3252S  [SOT23-6P_TMI3252S]  51.3 10.8 270 bottom
U52  TMI3252S  [SOT23-6P_TMI3252S]  39.8 10.8 270 top
U53  TMI3252S  [SOT23-6P_TMI3252S]  50.5 10.8 270 top
U54  TMI6050-18  [SOT23-5_TMI6050]  74.8 36.2 180 bottom
U55  OPEN-TMI6050-18  [SOT23-5_TMI6050]  48.7 33.9 270 bottom
U201  WA20-6829B  [QFN40_P0_5_W6_WA20-6829B]  90.43 54.05 0 bottom
U202  WA20-6829B  [QFN40_P0_5_W6_WA20-6829B]  90.43 32.11 0 bottom
U301  WA20-6829B  [QFN40_P0_5_W6_WA20-6829B]  26.62 31.09 180 bottom
U302  WA20-6829B  [QFN40_P0_5_W6_WA20-6829B]  26.62 53.04 180 bottom
UNK1R1  103/F/1005  [R1005]  51.5 5.9 90 bottom
UNK1R2  103/F/1005  [R1005]  39.8 5.5 90 top
UNK2C1  105P/6.3V/1005  [C0402]  65.23 47.98 225 bottom
UNK2C2  222P/16V/1005  [C0402]  59.94 47.52 270 bottom
UNK2C3  150P/50V/1005  [C1005]  71.81 50.98 180 top
UNK2C4  106P/6.3V/1608  [C0603]  55.4 47.88 90 bottom
UNK2C5  104P/16V/1005  [C0402]  66.52 50.32 180 bottom
UNK2C6  106P/6.3V/1608  [C0603]  53.7 47.88 90 bottom
UNK2C7  104P/16V/1005  [C0402]  56.72 47.65 270 bottom
UNK2C8  104P/16V/1005  [C0402]  57.81 47.7 270 bottom
UNK2C9  150P/50V/1005  [C1005]  71.81 52.12 180 top
UNK2C10  105P/6.3V/1005  [C0402]  66.04 46.28 315 bottom
UNK2C11  105P/6.3V/1005  [C0402]  56.41 45.34 90 bottom
UNK2C12  105P/6.3V/1005  [C0402]  69.14 47.07 270 bottom
UNK2C13  106P/6.3V/1608  [C0603]  55.08 44.75 270 bottom
UNK2C14  105P/6.3V/1005  [C0402]  58.88 47.7 270 bottom
UNK2C15  104P/16V/1005  [C1005]  67.6 60.25 0 top
UNK2C16  105P/6.3V/1005  [C0402]  63.65 45.82 0 bottom
UNK2C17  106P/6.3V/1608  [C0603]  70.54 46.66 90 bottom
UNK2C19  104P/16V/1005  [C0402]  61.21 47.52 270 bottom
UNK2C20  105P/6.3V/1005  [C0402]  61.09 45.85 180 bottom
UNK2C22  104P/16V/1005  [C0402]  59.31 51.13 0 bottom
UNK2CON1  OPEN-HB11041  [HDR_4P]  54.85 71.5 0 top
UNK2D3  SZESD7371HT1G  [SOD-323_SZESD7371HT1G]  56.2 65.21 180 top
UNK2D4  SZESD7371HT1G  [SOD-323_SZESD7371HT1G]  62.6 65.21 0 top
UNK2D7  OPEN-BL-HG036A-AV-TRB  [LED1608]  56 62.2 90 top
UNK2Q1  OPEN-MMBT3904  [SOT23_LRT_MMBT3904]  60.2 62.4 180 top
UNK2R1  241/1005  [R1005]  59.96 65.21 270 top
UNK2R2  OPEN-103/1005  [R0402]  57.25 50.39 0 bottom
UNK2R3  753/F/1005  [R0402]  69.8 52.73 90 bottom
UNK2R5  474/F/1005  [R1005]  70.18 51.51 90 top
UNK2R8  OPEN-473/1005  [R1005]  63.3 63.5 0 top
UNK2R10  220/F/1005  [R1005]  71.4 53.21 180 top
UNK2R12  OPEN-241/F/1005  [R1005]  57.8 62.4 270 top
UNK2R14  OPEN-104/1005  [R1005]  66.19 55.47 0 top
UNK2R15  243/F/1005  [R0402]  70.31 51.1 180 bottom
UNK2R16  241/1005  [R1005]  58.84 65.21 270 top
UNK2R18  152/1005  [R1005]  49.3 58.8 0 bottom
UNK2R19  152/1005  [R1005]  49.3 55.5 0 bottom
UNK2R24  152/1005  [R1005]  73.9 59.05 0 top
UNK2R27  000/1005  [TEST_R]  64.95 46.96 180 bottom
UNK2R28  152/1005  [R1005]  73.9 57.95 0 top
UNK2R29  472/1005  [R1005]  71.25 49.05 0 bottom
UNK2T3  T_POINT_R_1  [TP0_8PI]  55.2 50.6 270 top
UNK2T5  T_POINT_R_1  [TP0_8PI]  70.21 58.72 0 top
UNK2T6  T_POINT_R_1  [TP0_8PI]  68.28 53.85 0 top
UNK2T7  T_POINT_R_1  [TP0_8PI]  70.21 60.1 0 top
UNK2T8  T_POINT_R_1  [TP0_8PI]  71.53 58.72 0 top
UNK2T15  T_POINT_R_1  [TP1_0PI]  38 63.6 270 bottom
UNK2T16  T_POINT_R_1  [TP1_0PI]  38 61.6 270 bottom
UNK2T17  T_POINT_R_1  [TP1_0PI]  40 63.6 270 bottom
UNK2T18  T_POINT_R_1  [TP1_0PI]  40 61.6 270 bottom
UNK2T19  T_POINT_R_1  [TP1_0PI]  42 63.6 270 bottom
UNK2T20  T_POINT_R_1  [TP1_0PI]  42 61.6 270 bottom
UNK2T21  T_POINT_R_1  [TP1_0PI]  44 63.6 270 bottom
UNK2T22  T_POINT_R_1  [TP1_0PI]  44 61.6 270 bottom
UNK2T23  T_POINT_R_1  [TP1_0PI]  46 63.6 270 bottom
UNK2T24  T_POINT_R_1  [TP1_0PI]  46 61.6 270 bottom
UNK2T25  T_POINT_R_1  [TP1_0PI]  48 63.6 270 bottom
UNK2T26  T_POINT_R_1  [TP1_0PI]  48 61.6 270 bottom
UNK2T27  T_POINT_R_1  [TP1_0PI]  50 63.6 270 bottom
UNK2T28  T_POINT_R_1  [TP1_0PI]  50 61.6 270 bottom
UNK2T29  T_POINT_R_1  [TP0_8PI]  63.7 54.15 180 bottom
UNK2U2  DIO6809RST3  [SOT23_LRT_DIO6809RST3]  67.13 57.88 270 top
UNK2Y2  24MHz_CL12PF_3225  [XTAL3225]  75.06 52.04 0 top
UNK3C1  105P/6.3V/1005  [C0402]  68.1 46.66 270 bottom
UNK3C2  105P/6.3V/1005  [C0402]  56.02 32.25 270 bottom
UNK3C4  104P/16V/1005  [C0402]  65.05 43.31 180 bottom
UNK3C5  105P/6.3V/1005  [C0402]  61.98 44.27 270 bottom
UNK3C6  106P/6.3V/1608  [C0603]  57.65 25.43 90 bottom
UNK3C7  2R2P/50V/1005  [C0402]  64.21 38.07 225 top
UNK3C8  106P/6.3V/1608  [C0603]  60.78 31.09 90 bottom
UNK3C9  104P/16V/1005  [C0402]  56.95 35.31 0 bottom
UNK3C10  104P/16V/1005  [C0402]  59.06 35.31 180 bottom
UNK3C11  104P/16V/1005  [C0402]  58 31.85 0 bottom
UNK3C12  105P/6.3V/1005  [C0402]  63.65 23.7 90 bottom
UNK3C18  105P/6.3V/1005  [C0402]  55.97 26.01 270 bottom
UNK3C19  105P/6.3V/1005  [C0402]  57.38 30.21 270 bottom
UNK3C20  104P/16V/1005  [C0402]  63.02 36.02 180 bottom
UNK3C21  105P/6.3V/1005  [C0402]  57.16 33.69 270 bottom
UNK3C26  106P/6.3V/1608  [C0603]  58.7 29.74 90 bottom
UNK3C27  104P/16V/1005  [C0402]  55.99 30.19 270 bottom
UNK3C28  106P/6.3V/1608  [C0603]  56.11 40.31 135 bottom
UNK3C30  102P/50V/1005  [C0402]  64.72 25.12 90 bottom
UNK3C31  104P/16V/1005  [C0402]  57.86 42.21 315 bottom
UNK3C35  105P/6.3V/1005  [C0402]  55.97 23.93 270 bottom
UNK3C38  105P/6.3V/1005  [C0402]  62.79 32.85 0 bottom
UNK3C39  104P/16V/1005  [C0402]  60.53 43.87 270 bottom
UNK3C40  104P/16V/1005  [C0402]  61.1 25.9 0 bottom
UNK3C42  104P/16V/1005  [C0402]  62.8 33.96 0 bottom
UNK3C45  104P/16V/1005  [C0402]  63.09 29.62 0 bottom
UNK3C46  105P/6.3V/1005  [C0402]  57.68 22.05 0 bottom
UNK3C58  101P/50V/1005  [C0402]  64.36 34.34 270 bottom
UNK3C62  105P/6.3V/1005  [C0402]  58.79 43.01 315 bottom
UNK3R2  OPEN-151/1005  [R0402]  60.74 28.52 270 bottom
UNK3R6  241/F/1005  [R0402]  63.09 43.99 270 bottom
UNK3R8  OPEN-103/1005  [R0402]  57.73 23.37 180 bottom
UNK3R10  241/F/1005  [R0402]  64.49 27.37 180 bottom
UNK3R19  102/F/1005  [R0402]  54.89 28.05 270 bottom
UNK3R20  102/F/1005  [R0402]  54.89 30.19 270 bottom
UNK3T1  T_POINT_R_1  [TP12]  63.97 43.29 180 bottom
UNK3U1  H5TC4G63CFR-RDC  [BGA96_H5TC4G63CFR-RDC]  60.45 29.13 0 top
UNK4C2  105P/6.3V/1005  [C0402]  57.65 44.7 270 bottom
UNK4C3  OPEN-6R8P/50V/1005  [C1005]  52.43 43.79 0 top
UNK4C4  104P/16V/1005  [C1005]  49.2 29.7 0 top
UNK4C5  475P/6.3V/1608  [C1608]  38.85 29.3 0 top
UNK4C8  104P/16V/1005  [C1005]  42.8 51.85 90 bottom
UNK4C9  104P/16V/1005  [C1005]  47.6 31.1 180 bottom
UNK4C10  104P/16V/1005  [C1005]  45.54 53.62 180 top
UNK4C11  104P/16V/1005  [C1005]  48.75 52.75 180 top
UNK4C17  OPEN-104P/16V/1005  [C1005]  44.2 42.1 180 bottom
UNK4C18  OPEN-105P/6.3V/1005  [C1005]  45.65 40.35 180 bottom
UNK4C26  OPEN-105P/6.3V/1005  [C1005]  39.95 42.4 90 bottom
UNK4C34  OPEN-104P/16V/1005  [C1005]  44.2 43.2 180 bottom
UNK4C35  OPEN-105P/6.3V/1005  [C1005]  43.15 37.4 270 bottom
UNK4C47  OPEN-475P/6.3V/1608  [C1608]  44.4 37.65 90 bottom
UNK4C48  104P/16V/1005  [C1005]  39.15 51.35 90 bottom
UNK4C49  104P/16V/1005  [C1005]  44 29.7 180 bottom
UNK4K2  TS-1187-1716  [SW_TS-1187]  4.47 14.94 0 top
UNK4R1  OPEN-103/1005  [R1005]  42.15 35.55 90 bottom
UNK4R2  OPEN-472/1005  [R1005]  37.62 54.03 270 top
UNK4R3  000/1005  [R1005]  42.49 54.03 270 top
UNK4R4  473/1005  [R1005]  45.7 31.1 0 bottom
UNK4R5  OPEN-000/1005  [R1005]  45.9 36.5 270 bottom
UNK4R6  000/1005  [R1005]  47 36.5 270 bottom
UNK4R7  000/1005  [R1005]  44.65 53.5 180 bottom
UNK4R8  OPEN-000/1005  [R1005]  43.71 54.03 270 top
UNK4R9  OPEN-103/1005  [R1005]  38.8 41.35 90 bottom
UNK4R10  472/1005  [R1005]  40.06 54.03 270 top
UNK4R11  OPEN-000/1005  [R1005]  54.86 43.79 0 top
UNK4R12  103/1005  [R1005]  39.25 39.8 0 bottom
UNK4R13  OPEN-472/1005  [R1005]  38.84 54.03 270 top
UNK4R14  OPEN-472/1005  [R1005]  41.05 35.55 270 bottom
UNK4R15  OPEN-000/1005  [R1005]  53.65 40.5 0 top
UNK4R16  OPEN-472/1005  [R1005]  44.4 44.7 90 bottom
UNK4R17  OPEN-000/1005  [R1005]  40.3 40.9 0 bottom
UNK4R18  OPEN-000/1005  [R1005]  53.65 41.6 0 top
UNK4R19  OPEN-000/1005  [R1005]  54.89 49.05 0 top
UNK4R20  OPEN-000/1005  [R1005]  52.45 49.05 0 top
UNK4R21  OPEN-000/1005  [R1005]  54.89 47.83 0 top
UNK4R22  OPEN-000/1005  [R1005]  52.45 47.83 0 top
UNK4R23  OPEN-000/1005  [R1005]  54.89 46.61 0 top
UNK4R24  OPEN-000/1005  [R1005]  52.45 46.61 0 top
UNK4R25  OPEN-000/1005  [R1005]  54.89 45.39 0 top
UNK4R26  OPEN-000/1005  [R1005]  52.45 45.39 0 top
UNK4R52  OPEN-472/1005  [R1005]  41.28 54.03 270 top
UNK4T25  T_POINT_R_1  [TP0_8PI]  53.05 40.75 180 bottom
UNK4U5  MX30LF4G28AD_TI  [TSOP48_W20_MX30LF4G28AD-TI]  43.89 41.35 90 top
UNK4U9  OPEN-S40FC004C181C  [BGA153_S40FC004C181C]  43.76 41.35 0 top
UNK5C3  105P/6.3V/1005  [C1005]  74.6 42.55 180 top
UNK5C9  104P/16V/1005  [C0402]  65.33 44.93 90 bottom
UNK5C10  104P/16V/1005  [C0402]  68.3 44.98 180 bottom
UNK5C11  105P/6.3V/1005  [C1005]  72.4 43.4 0 top
UNK5C13  104P/16V/1005  [C1005]  96.7 7 180 bottom
UNK5D11  SZESD7371HT1G  [SOD-323_SZESD7371HT1G]  83.75 15.55 90 bottom
UNK5D12  SZESD7371HT1G  [SOD-323_SZESD7371HT1G]  85.55 15.55 90 bottom
UNK5R5  102/1005  [R1005]  72.85 41.85 90 top
UNK5R20  OPEN-103/1005  [R1005]  75.3 40.25 180 bottom
UNK5R64  201/F/1005  [R0402]  71.2 44.55 0 bottom
UNK5R65  101/1005  [R1005]  80.9 11.7 90 bottom
UNK5R66  101/1005  [R1005]  80.9 14.6 90 bottom
UNK5R67  201/1005  [R1005]  79.7 11.7 90 bottom
UNK5R68  201/1005  [R1005]  78.5 11.7 90 bottom
UNK5R69  101/1005  [R1005]  78.1 14.2 90 bottom
UNK5R70  OPEN-101/1005  [R1005]  77.15 11.75 90 bottom
UNK5R71  5R1/F/1005  [R1005]  85.6 11.7 90 bottom
UNK5R72  5R1/F/1005  [R1005]  84.5 11.7 90 bottom
UNK5R73  101/1005  [R1005]  83.1 11.7 90 bottom
UNK5R74  101/1005  [R1005]  82 11.7 90 bottom
UNK5R75  101/1005  [R1005]  82 14.6 90 bottom
UNK5R76  OPEN-101/1005  [R1005]  80.9 17.15 90 bottom
UNK5R77  OPEN-101/1005  [R1005]  82 17.15 90 bottom
UNK5R78  OPEN-103/1005  [R1005]  74.6 41.45 0 top
UNK5R83  102/1005  [R1005]  82.65 18.2 180 top
UNK5R84  5R1/F/1005  [R1005]  85.75 16.15 180 top
UNK5R85  5R1/F/1005  [R1005]  85.75 17.35 180 top

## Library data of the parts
C1-C4 C21 C22 C30 C76-C79 C201 C203 C206 C207 C209 C211 C213 C214 C216 C218 C219 C221 C224 C228-C231 C233 C235 C237 C238 C240 C242 C243 C245 C248 C249 C255-C270 C301 C303 C306 C307 C309 C311 C313 C314 C316 C318 C319 C321 C324 C328-C331 C333 C335 C337 C338 C340 C342 C343 C345 C348 C353-C368 UNK2C4 UNK2C6 UNK2C13 UNK2C17 UNK3C6 UNK3C8 UNK3C26 UNK3C28 UNK4C5 UNK4C47 = MLCC 1608_0
C5 C9 C10 C12 C14 C15 C17 C19 C20 C23-C25 C52 C53 C55 C58 C59 C61 C63-C67 C69 C70 C72 C74 C75 C101-C106 C202 C204 C208 C210 C215 C217 C220 C222 C225 C226 C232 C234 C239 C241 C244 C246 C250-C254 C302 C304 C308 C310 C315 C317 C320 C322 C325 C326 C332 C334 C339 C341 C344 C346 C349-C352 UNK2C1-UNK2C3 UNK2C5 UNK2C7-UNK2C12 UNK2C14-UNK2C16 UNK2C19 UNK2C20 UNK2C22 UNK3C1 UNK3C2 UNK3C4 UNK3C5 UNK3C7 UNK3C9-UNK3C12 UNK3C18-UNK3C21 UNK3C27 UNK3C30 UNK3C31 UNK3C35 UNK3C38-UNK3C40 UNK3C42 UNK3C45 UNK3C46 UNK3C58 UNK3C62 UNK4C2-UNK4C4 UNK4C8-UNK4C11 UNK4C17 UNK4C18 UNK4C26 UNK4C34 UNK4C35 UNK4C48 UNK4C49 UNK5C3 UNK5C9-UNK5C11 UNK5C13 = MLCC 1005_0
C6 C7 C13 C16 C18 C51 C54 C56 C57 C60 C62 C68 C71 C73 = MLCC 2012_0
C205 C223 C305 C323 = ECAP-2.5X6.3-D
FB201-FB204 FB301-FB304 = BEAD
J803 J804 = CON4
J812 = CON HEADER 1X4_1
J813 = CON15X1-4G_0
J814 = JP_USB-0400ASMT_0
L1 L2 L51-L53 L201-L204 L211-L214 L301-L304 L311-L314 = INDUCTOR CHIP_0
Q1 = P-MOSFET
Q2-Q5 UNK2Q1 = npn
R1-R3 R6-R13 R15-R19 R21 R22 R51-R63 R101-R110 R201-R217 R219-R231 R233-R236 R238-R240 R301-R317 R319-R344 R348-R351 UNK1R1 UNK1R2 UNK2R1-UNK2R3 UNK2R5 UNK2R8 UNK2R10 UNK2R12 UNK2R14-UNK2R16 UNK2R18 UNK2R19 UNK2R24 UNK2R27-UNK2R29 UNK3R2 UNK3R6 UNK3R8 UNK3R10 UNK3R19 UNK3R20 UNK4R1-UNK4R26 UNK4R52 UNK5R5 UNK5R20 UNK5R64-UNK5R70 UNK5R73-UNK5R78 UNK5R83 = RES-V
T1 = FILTER EMI DLW21SN900SQ2_0
T101-T116 T120 T125-T127 T129 T201-T204 T301-T331 UNK2T3 UNK2T5-UNK2T8 UNK2T15-UNK2T29 UNK3T1 UNK4T25 = T_POINT_R_1
U1 = A113X_20170516_V17
U2 = MP2338GTL_0
U3 U51-U53 = SY81XX
U54 U55 = WL2003E
U201 U202 U301 U302 = WA20-6829B_0
UNK2CON1 = CN-4P_0
UNK2D3 UNK2D4 UNK5D11 UNK5D12 = TVS DIODE
UNK2D7 = LED_3
UNK2U2 = MAX809RD
UNK2Y2 = SMD_CRYSTAL
UNK3U1 = DDR3_96P_16b_0
UNK4K2 = BUTTON_0
UNK4U5 = NAND-ALL_11
UNK4U9 = eMMC_V5_0.1
UNK5R71 UNK5R72 UNK5R84 UNK5R85 = RES-V: signal model: RES-V_R1005_5R1/F/1005_5R1/F/1005

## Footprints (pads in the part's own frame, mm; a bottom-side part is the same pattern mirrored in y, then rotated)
51318-0023L-001
  round 2.8 hole 1.8: 1(1.98,-7.2) 2(-1.98,-7.2)
A113X
  round 0.3 smd: A1(-5.2,5.2) A2(-4.55,5.2) A3(-3.9,5.2) A4(-3.25,5.2) A5(-2.6,5.2) A6(-1.95,5.2) A7(-1.3,5.2) A8(-0.65,5.2) A9(0,5.2) A10(0.65,5.2) A11(1.3,5.2) A12(1.95,5.2) A13(2.6,5.2) A14(3.25,5.2) A15(3.9,5.2) A16(4.55,5.2) A17(5.2,5.2) B1(-5.2,4.55) B2(-4.55,4.55) B3(-3.9,4.55) B4(-3.25,4.55) B5(-2.6,4.55) B6(-1.95,4.55) B7(-1.3,4.55) B8(-0.65,4.55) B9(0,4.55) B10(0.65,4.55) B11(1.3,4.55) B12(1.95,4.55) B13(2.6,4.55) B14(3.25,4.55) B15(3.9,4.55) B16(4.55,4.55) B17(5.2,4.55) C1(-5.2,3.9) C2(-4.55,3.9) C3(-3.9,3.9) C4(-3.25,3.9) C5(-2.6,3.9) C6(-1.95,3.9) C7(-1.3,3.9) C8(-0.65,3.9) C9(0,3.9) C10(0.65,3.9) C11(1.3,3.9) C12(1.95,3.9) C13(2.6,3.9) C15(3.9,3.9) C16(4.55,3.9) C17(5.2,3.9) D1(-5.2,3.25) D2(-4.55,3.25) D3(-3.9,3.25) D4(-3.25,3.25) D5(-2.6,3.25) D6(-1.95,3.25) D7(-1.3,3.25) D8(-0.65,3.25) D9(0,3.25) D10(0.65,3.25) D11(1.3,3.25) D12(1.95,3.25) D13(2.6,3.25) D14(3.25,3.25) D15(3.9,3.25) D16(4.55,3.25) D17(5.2,3.25) E2(-4.55,2.6) E3(-3.9,2.6) E4(-3.25,2.6) E5(-2.6,2.6) E6(-1.95,2.6) E7(-1.3,2.6) E8(-0.65,2.6) E9(0,2.6) E10(0.65,2.6) E11(1.3,2.6) E12(1.95,2.6) E13(2.6,2.6) E14(3.25,2.6) E15(3.9,2.6) E16(4.55,2.6) E17(5.2,2.6) F1(-5.2,1.95) F2(-4.55,1.95) F3(-3.9,1.95) F4(-3.25,1.95) F5(-2.6,1.95) F6(-1.95,1.95) F7(-1.3,1.95) F8(-0.65,1.95) F9(0,1.95) F10(0.65,1.95) F11(1.3,1.95) F12(1.95,1.95) F13(2.6,1.95) F14(3.25,1.95) F15(3.9,1.95) F16(4.55,1.95) F17(5.2,1.95) G1(-5.2,1.3) G2(-4.55,1.3) G3(-3.9,1.3) G4(-3.25,1.3) G5(-2.6,1.3) G6(-1.95,1.3) G7(-1.3,1.3) G8(-0.65,1.3) G9(0,1.3) G10(0.65,1.3) G11(1.3,1.3) G12(1.95,1.3) G13(2.6,1.3) G14(3.25,1.3) G15(3.9,1.3) G16(4.55,1.3) G17(5.2,1.3) H1(-5.2,0.65) H2(-4.55,0.65) H3(-3.9,0.65) H4(-3.25,0.65) H5(-2.6,0.65) H6(-1.95,0.65) H7(-1.3,0.65) H8(-0.65,0.65) H9(0,0.65) H10(0.65,0.65) H11(1.3,0.65) H12(1.95,0.65) H13(2.6,0.65) H14(3.25,0.65) H15(3.9,0.65) H16(4.55,0.65) H17(5.2,0.65) J1(-5.2,0) J2(-4.55,0) J3(-3.9,0) J4(-3.25,0) J5(-2.6,0) J6(-1.95,0) J7(-1.3,0) J8(-0.65,0) J9(0,0) J10(0.65,0) J11(1.3,0) J12(1.95,0) J13(2.6,0) J14(3.25,0) J15(3.9,0) J16(4.55,0) J17(5.2,0) K1(-5.2,-0.65) K2(-4.55,-0.65) K3(-3.9,-0.65) K4(-3.25,-0.65) K5(-2.6,-0.65) K6(-1.95,-0.65) K7(-1.3,-0.65) K8(-0.65,-0.65) K9(0,-0.65) K10(0.65,-0.65) K11(1.3,-0.65) K12(1.95,-0.65) K13(2.6,-0.65) K14(3.25,-0.65) K15(3.9,-0.65) K16(4.55,-0.65) K17(5.2,-0.65) L1(-5.2,-1.3) L2(-4.55,-1.3) L3(-3.9,-1.3) L4(-3.25,-1.3) L5(-2.6,-1.3) L6(-1.95,-1.3) L7(-1.3,-1.3) L8(-0.65,-1.3) L9(0,-1.3) L11(1.3,-1.3) L12(1.95,-1.3) L13(2.6,-1.3) L14(3.25,-1.3) L15(3.9,-1.3) L16(4.55,-1.3) L17(5.2,-1.3) M1(-5.2,-1.95) M2(-4.55,-1.95) M3(-3.9,-1.95) M4(-3.25,-1.95) M5(-2.6,-1.95) M6(-1.95,-1.95) M7(-1.3,-1.95) M8(-0.65,-1.95) M9(0,-1.95) M10(0.65,-1.95) M11(1.3,-1.95) M12(1.95,-1.95) M13(2.6,-1.95) M14(3.25,-1.95) M15(3.9,-1.95) M16(4.55,-1.95) M17(5.2,-1.95) N1(-5.2,-2.6) N2(-4.55,-2.6) N3(-3.9,-2.6) N4(-3.25,-2.6) N5(-2.6,-2.6) N6(-1.95,-2.6) N7(-1.3,-2.6) N8(-0.65,-2.6) N9(0,-2.6) N10(0.65,-2.6) N11(1.3,-2.6) N12(1.95,-2.6) N13(2.6,-2.6) N14(3.25,-2.6) N15(3.9,-2.6) N16(4.55,-2.6) P1(-5.2,-3.25) P2(-4.55,-3.25) P3(-3.9,-3.25) P4(-3.25,-3.25) P5(-2.6,-3.25) P6(-1.95,-3.25) P7(-1.3,-3.25) P8(-0.65,-3.25) P9(0,-3.25) P10(0.65,-3.25) P11(1.3,-3.25) P12(1.95,-3.25) P13(2.6,-3.25) P14(3.25,-3.25) P15(3.9,-3.25) P16(4.55,-3.25) P17(5.2,-3.25) R1(-5.2,-3.9) R2(-4.55,-3.9) R3(-3.9,-3.9) R4(-3.25,-3.9) R5(-2.6,-3.9) R6(-1.95,-3.9) R7(-1.3,-3.9) R8(-0.65,-3.9) R9(0,-3.9) R10(0.65,-3.9) R11(1.3,-3.9) R12(1.95,-3.9) R13(2.6,-3.9) R14(3.25,-3.9) R15(3.9,-3.9) R16(4.55,-3.9) R17(5.2,-3.9) T1(-5.2,-4.55) T2(-4.55,-4.55) T3(-3.9,-4.55) T4(-3.25,-4.55) T5(-2.6,-4.55) T6(-1.95,-4.55) T7(-1.3,-4.55) T8(-0.65,-4.55) T9(0,-4.55) T10(0.65,-4.55) T11(1.3,-4.55) T12(1.95,-4.55) T13(2.6,-4.55) T14(3.25,-4.55) T15(3.9,-4.55) T16(4.55,-4.55) T17(5.2,-4.55) U1(-5.2,-5.2) U2(-4.55,-5.2) U3(-3.9,-5.2) U4(-3.25,-5.2) U5(-2.6,-5.2) U6(-1.95,-5.2) U7(-1.3,-5.2) U9(0,-5.2) U10(0.65,-5.2) U11(1.3,-5.2) U12(1.95,-5.2) U13(2.6,-5.2) U14(3.25,-5.2) U15(3.9,-5.2) U16(4.55,-5.2) U17(5.2,-5.2)
BGA96_H5TC4G63CFR-RDC
  round 0.4 smd: A1(-3.2,6) A2(-2.4,6) A3(-1.6,6) A7(1.6,6) A8(2.4,6) A9(3.2,6) B1(-3.2,5.2) B2(-2.4,5.2) B3(-1.6,5.2) B7(1.6,5.2) B8(2.4,5.2) B9(3.2,5.2) C1(-3.2,4.4) C2(-2.4,4.4) C3(-1.6,4.4) C7(1.6,4.4) C8(2.4,4.4) C9(3.2,4.4) D1(-3.2,3.6) D2(-2.4,3.6) D3(-1.6,3.6) D7(1.6,3.6) D8(2.4,3.6) D9(3.2,3.6) E1(-3.2,2.8) E2(-2.4,2.8) E3(-1.6,2.8) E7(1.6,2.8) E8(2.4,2.8) E9(3.2,2.8) F1(-3.2,2) F2(-2.4,2) F3(-1.6,2) F7(1.6,2) F8(2.4,2) F9(3.2,2) G1(-3.2,1.2) G2(-2.4,1.2) G3(-1.6,1.2) G7(1.6,1.2) G8(2.4,1.2) G9(3.2,1.2) H1(-3.2,0.4) H2(-2.4,0.4) H3(-1.6,0.4) H7(1.6,0.4) H8(2.4,0.4) H9(3.2,0.4) J1(-3.2,-0.4) J2(-2.4,-0.4) J3(-1.6,-0.4) J7(1.6,-0.4) J8(2.4,-0.4) J9(3.2,-0.4) K1(-3.2,-1.2) K2(-2.4,-1.2) K3(-1.6,-1.2) K7(1.6,-1.2) K8(2.4,-1.2) K9(3.2,-1.2) L1(-3.2,-2) L2(-2.4,-2) L3(-1.6,-2) L7(1.6,-2) L8(2.4,-2) L9(3.2,-2) M1(-3.2,-2.8) M2(-2.4,-2.8) M3(-1.6,-2.8) M7(1.6,-2.8) M8(2.4,-2.8) M9(3.2,-2.8) N1(-3.2,-3.6) N2(-2.4,-3.6) N3(-1.6,-3.6) N7(1.6,-3.6) N8(2.4,-3.6) N9(3.2,-3.6) P1(-3.2,-4.4) P2(-2.4,-4.4) P3(-1.6,-4.4) P7(1.6,-4.4) P8(2.4,-4.4) P9(3.2,-4.4) R1(-3.2,-5.2) R2(-2.4,-5.2) R3(-1.6,-5.2) R7(1.6,-5.2) R8(2.4,-5.2) R9(3.2,-5.2) T1(-3.2,-6) T2(-2.4,-6) T3(-1.6,-6) T7(1.6,-6) T8(2.4,-6) T9(3.2,-6)
BGA153_S40FC004C181C
  round 0.3 smd: A4(-1.75,6.75) A6(-0.75,6.75) A9(0.75,6.75) A11(1.75,6.75) AA1(-3.25,-3.25) AA2(-2.75,-3.25) AA3(-2.25,-3.25) AA4(-1.75,-3.25) AA5(-1.25,-3.25) AA6(-0.75,-3.25) AA7(-0.25,-3.25) AA8(0.25,-3.25) AA9(0.75,-3.25) AA10(1.25,-3.25) AA11(1.75,-3.25) AA12(2.25,-3.25) AA13(2.75,-3.25) AA14(3.25,-3.25) AE1(-3.25,-5.25) AE14(3.25,-5.25) AG2(-2.75,-6.25) AG13(2.75,-6.25) AH4(-1.75,-6.75) AH6(-0.75,-6.75) AH9(0.75,-6.75) AH11(1.75,-6.75) B2(-2.75,6.25) B13(2.75,6.25) D1(-3.25,5.25) D14(3.25,5.25) H1(-3.25,3.25) H2(-2.75,3.25) H3(-2.25,3.25) H4(-1.75,3.25) H5(-1.25,3.25) H6(-0.75,3.25) H7(-0.25,3.25) H8(0.25,3.25) H9(0.75,3.25) H10(1.25,3.25) H11(1.75,3.25) H12(2.25,3.25) H13(2.75,3.25) H14(3.25,3.25) J1(-3.25,2.75) J2(-2.75,2.75) J3(-2.25,2.75) J4(-1.75,2.75) J5(-1.25,2.75) J6(-0.75,2.75) J7(-0.25,2.75) J8(0.25,2.75) J9(0.75,2.75) J10(1.25,2.75) J11(1.75,2.75) J12(2.25,2.75) J13(2.75,2.75) J14(3.25,2.75) K1(-3.25,2.25) K2(-2.75,2.25) K3(-2.25,2.25) K4(-1.75,2.25) K5(-1.25,2.25) K6(-0.75,2.25) K7(-0.25,2.25) K8(0.25,2.25) K9(0.75,2.25) K10(1.25,2.25) K11(1.75,2.25) K12(2.25,2.25) K13(2.75,2.25) K14(3.25,2.25) L1(-3.25,1.75) L2(-2.75,1.75) L3(-2.25,1.75) L4(-1.75,1.75) L12(2.25,1.75) L13(2.75,1.75) L14(3.25,1.75) M1(-3.25,1.25) M2(-2.75,1.25) M3(-2.25,1.25) M5(-1.25,1.25) M6(-0.75,1.25) M7(-0.25,1.25) M8(0.25,1.25) M9(0.75,1.25) M10(1.25,1.25) M12(2.25,1.25) M13(2.75,1.25) M14(3.25,1.25) N1(-3.25,0.75) N2(-2.75,0.75) N3(-2.25,0.75) N5(-1.25,0.75) N10(1.25,0.75) N12(2.25,0.75) N13(2.75,0.75) N14(3.25,0.75) P1(-3.25,0.25) P2(-2.75,0.25) P3(-2.25,0.25) P5(-1.25,0.25) P10(1.25,0.25) P12(2.25,0.25) P13(2.75,0.25) P14(3.25,0.25) R1(-3.25,-0.25) R2(-2.75,-0.25) R3(-2.25,-0.25) R5(-1.25,-0.25) R10(1.25,-0.25) R12(2.25,-0.25) R13(2.75,-0.25) R14(3.25,-0.25) T1(-3.25,-0.75) T2(-2.75,-0.75) T3(-2.25,-0.75) T5(-1.25,-0.75) T10(1.25,-0.75) T12(2.25,-0.75) T13(2.75,-0.75) T14(3.25,-0.75) U1(-3.25,-1.25) U2(-2.75,-1.25) U3(-2.25,-1.25) U5(-1.25,-1.25) U6(-0.75,-1.25) U7(-0.25,-1.25) U8(0.25,-1.25) U9(0.75,-1.25) U10(1.25,-1.25) U12(2.25,-1.25) U13(2.75,-1.25) U14(3.25,-1.25) V1(-3.25,-1.75) V2(-2.75,-1.75) V3(-2.25,-1.75) V12(2.25,-1.75) V13(2.75,-1.75) V14(3.25,-1.75) W1(-3.25,-2.25) W2(-2.75,-2.25) W3(-2.25,-2.25) W4(-1.75,-2.25) W5(-1.25,-2.25) W6(-0.75,-2.25) W7(-0.25,-2.25) W8(0.25,-2.25) W9(0.75,-2.25) W10(1.25,-2.25) W11(1.75,-2.25) W12(2.25,-2.25) W13(2.75,-2.25) W14(3.25,-2.25) Y1(-3.25,-2.75) Y2(-2.75,-2.75) Y3(-2.25,-2.75) Y4(-1.75,-2.75) Y5(-1.25,-2.75) Y6(-0.75,-2.75) Y7(-0.25,-2.75) Y8(0.25,-2.75) Y9(0.75,-2.75) Y10(1.25,-2.75) Y11(1.75,-2.75) Y12(2.25,-2.75) Y13(2.75,-2.75) Y14(3.25,-2.75)
BLM21
  rect 0.8x1.3 smd: 1(-0.8,0) 2(0.8,0)
C0402
  rect 0.508x0.508 smd: 1(-0.508,0) 2(0.508,0)
C0603
  rect 0.813x0.864 smd: 1(-0.762,0) 2(0.762,0)
C1005
  rect 0.5x0.6 smd: 1(-0.45,0) 2(0.45,0)
C1608
  rect 0.6x0.9 smd: 1(-0.7,0) 2(0.7,0)
C2012
  rect 0.8x1.4 smd: 1(-0.85,0) 2(0.85,0)
C3216
  rect 1x1.7 smd: 1(-1.5,0) 2(1.5,0)
C3225
  rect 1.6x2.7 smd: 1(-1.3,0) 2(1.3,0)
CIS2012
  rect 0.8x1.4 smd: 1(-0.85,0) 2(0.85,0)
COIL_BPPM00121190
  rect 3.6x3.2 smd: 1(-5.1,2.65) 2(-5.1,-2.65) 3(5.1,-2.65) 4(5.1,2.65)
COIL_LVS404018
  rect 4.3x1.7 smd: 1(0,1.45) 2(0,-1.45)
COIL_MLPS5035
  rect 5.4x1.95 smd: 1(0,1.725) 2(0,-1.725)
COIL_SMPI0402BW
  rect 1.5x2.5 smd: 1(-1.85,0) 2(1.85,0)
COIL_SPH10040
  rect 3.1x3.8 smd: 1(-5,0) 2(5,0)
ECAP_8PI_H10
  oval 4.6x2.2 smd: 1(3.35,0) 2(-3.35,0)
FH41-15S-0_5SH
  rect 0.25x0.65 smd: 1(3.5,-3.2) 2(3,-3.2) 3(2.5,-3.2) 4(2,-3.2) 5(1.5,-3.2) 6(1,-3.2) 7(0.5,-3.2) 8(0,-3.2) 9(-0.5,-3.2) 10(-1,-3.2) 11(-1.5,-3.2) 12(-2,-3.2) 13(-2.5,-3.2) 14(-3,-3.2) 15(-3.5,-3.2)
  rect 0.4x1.55 smd: S1(-4.75,2.05) S5(4.75,2.05)
  rect 0.2x1.2 smd: S2(-2.5,2.475) S3(0,2.475) S4(2.5,2.475)
HDR_4P
  round 1.7 hole 1.1: 1(0,0) 2(2.54,0) 3(5.08,0) 4(7.62,0)
LED1608
  rect 0.9x1 smd: 1(-0.75,0) 2(0.75,0)
MICRO_USB_10118192
  rect 0.4x1.35 smd: 1(-1.3,2.325) 2(-0.65,2.325) 3(0,2.325) 4(0.65,2.325) 5(1.3,2.325)
  rect 2.1x1.6 smd: 6(-3.1,2.2) 7(3.1,2.2)
  rect 1.8x1.9 smd: 8(-3.8,-0.35) 9(-1.15,-0.35) 10(1.15,-0.35) 11(3.8,-0.35)
QFN40_P0_5_W6_WA20-6829B
  oval 0.7x0.38 smd: 1(-2.9,2.25) 2(-2.9,1.75) 3(-2.9,1.25) 4(-2.9,0.75) 5(-2.9,0.25) 6(-2.9,-0.25) 7(-2.9,-0.75) 8(-2.9,-1.25) 9(-2.9,-1.75) 10(-2.9,-2.25) 21(2.9,-2.25) 22(2.9,-1.75) 23(2.9,-1.25) 24(2.9,-0.75) 25(2.9,-0.25) 26(2.9,0.25) 27(2.9,0.75) 28(2.9,1.25) 29(2.9,1.75) 30(2.9,2.25)
  oval 0.38x0.7 smd: 11(-2.25,-2.9) 12(-1.75,-2.9) 13(-1.25,-2.9) 14(-0.75,-2.9) 15(-0.25,-2.9) 16(0.25,-2.9) 17(0.75,-2.9) 18(1.25,-2.9) 19(1.75,-2.9) 20(2.25,-2.9) 31(2.25,2.9) 32(1.75,2.9) 33(1.25,2.9) 34(0.75,2.9) 35(0.25,2.9) 36(-0.25,2.9) 37(-0.75,2.9) 38(-1.25,2.9) 39(-1.75,2.9) 40(-2.25,2.9)
  rect 4.6x3.4 smd: 41(0,0)
R0402
  rect 0.508x0.508 smd: 1(-0.508,0) 2(0.508,0)
R1005
  rect 0.5x0.6 smd: 1(-0.45,0) 2(0.45,0)
R1608
  rect 0.6x0.9 smd: 1(-0.7,0) 2(0.7,0)
R2012
  rect 0.8x1.4 smd: 1(-0.85,0) 2(0.85,0)
SOD-323_SZESD7371HT1G
  rect 0.8x0.5 smd: 1(-1.15,0) 2(1.15,0)
SOP8_EP_TMI3343B
  oval 1x1.4 smd: 1(-2.005,-2.8) 4(2.005,-2.8) 5(2.005,2.8) 8(-2.005,2.8)
  oval 0.8x1.4 smd: 2(-0.635,-2.8) 3(0.635,-2.8) 6(0.635,2.8) 7(-0.635,2.8)
  rect 3.5x2.6 smd: 9(0,0)
SOT23-5_TMI6050
  rect 0.6x0.8 smd: 1(-0.95,-1.3) 2(0,-1.3) 3(0.95,-1.3) 4(0.95,1.3) 5(-0.95,1.3)
SOT23-6P_TMI3252S
  rect 0.65x1 smd: 1(-1.025,-1.3) 3(1.025,-1.3) 4(1.025,1.3) 6(-1.025,1.3)
  rect 0.5x1 smd: 2(0,-1.3) 5(0,1.3)
SOT23_LRT_DIO6809RST3
  rect 0.7x0.7 smd: 1(-0.95,-1.1) 2(0.95,-1.1) 3(0,1.1)
SOT23_LRT_MMBT3904
  rect 0.7x0.7 smd: 1(-0.95,-1.1) 2(0.95,-1.1) 3(0,1.1)
SOT23_LRT_W2_7_WPM3401
  rect 0.7x0.9 smd: 1(-0.95,-1.2) 2(0.95,-1.2) 3(0,1.2)
SW_TS-1187
  rect 0.8x0.9 smd: 1(-3,1.85) 2(3,1.85) 3(-3,-1.85) 4(3,-1.85)
SWPA8040S
  rect 7.5x2.2 smd: 1(0,3) 2(0,-3)
SWPA8065S
  rect 7.5x2.2 smd: 1(0,3) 2(0,-3)
SXB-EH-4P
  round 1.5 hole 1: 1(-3.75,-3.7) 2(-1.25,-3.7) 3(1.25,-3.7) 4(3.75,-3.7)
TEST_R
  rect 0.203x0.203 smd: 1(-0.102,0) 2(0.102,0)
TP0_8PI
  round 0.8 smd: 1(0,0)
TP1_0PI
  round 1 smd: 1(0,0)
TP12
  round 0.3 smd: 1(0,0)
TSOP48_W20_MX30LF4G28AD-TI
  oval 1.6x0.25 smd: 1(-9.8,5.75) 2(-9.8,5.25) 3(-9.8,4.75) 4(-9.8,4.25) 5(-9.8,3.75) 6(-9.8,3.25) 7(-9.8,2.75) 8(-9.8,2.25) 9(-9.8,1.75) 10(-9.8,1.25) 11(-9.8,0.75) 12(-9.8,0.25) 13(-9.8,-0.25) 14(-9.8,-0.75) 15(-9.8,-1.25) 16(-9.8,-1.75) 17(-9.8,-2.25) 18(-9.8,-2.75) 19(-9.8,-3.25) 20(-9.8,-3.75) 21(-9.8,-4.25) 22(-9.8,-4.75) 23(-9.8,-5.25) 24(-9.8,-5.75) 25(9.8,-5.75) 26(9.8,-5.25) 27(9.8,-4.75) 28(9.8,-4.25) 29(9.8,-3.75) 30(9.8,-3.25) 31(9.8,-2.75) 32(9.8,-2.25) 33(9.8,-1.75) 34(9.8,-1.25) 35(9.8,-0.75) 36(9.8,-0.25) 37(9.8,0.25) 38(9.8,0.75) 39(9.8,1.25) 40(9.8,1.75) 41(9.8,2.25) 42(9.8,2.75) 43(9.8,3.25) 44(9.8,3.75) 45(9.8,4.25) 46(9.8,4.75) 47(9.8,5.25) 48(9.8,5.75)
unnamed#2
  round 1 smd: 1(0,0)
unnamed#3
  round 0.6 hole 0.6 unplated: (-2.5,0) (2.5,0)
  round 0.5 hole 0.5 unplated: (-1.5,0) (-0.5,0) (0.5,0) (1.5,0)
unnamed#4
  round 0.5 hole 0.5 unplated: (-1,0) (0,0) (1,0)
unnamed#5
  round 2.5 hole 2.5 unplated: (0,0)
XTAL3225
  rect 1.3x1.1 smd: 1(-1.15,-0.875) 2(1.15,-0.875) 3(1.15,0.875) 4(-1.15,0.875)

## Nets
5V_EN: C12.2 R1.1 R2.1 R2.2 R3.2 U2.7(EN) UNK5R73.2
